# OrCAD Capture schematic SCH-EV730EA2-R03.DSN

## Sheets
1 USB & POWER: size A3; title: EV730EA0_USB&POWER; rev: 6.0; note: Ver6.1
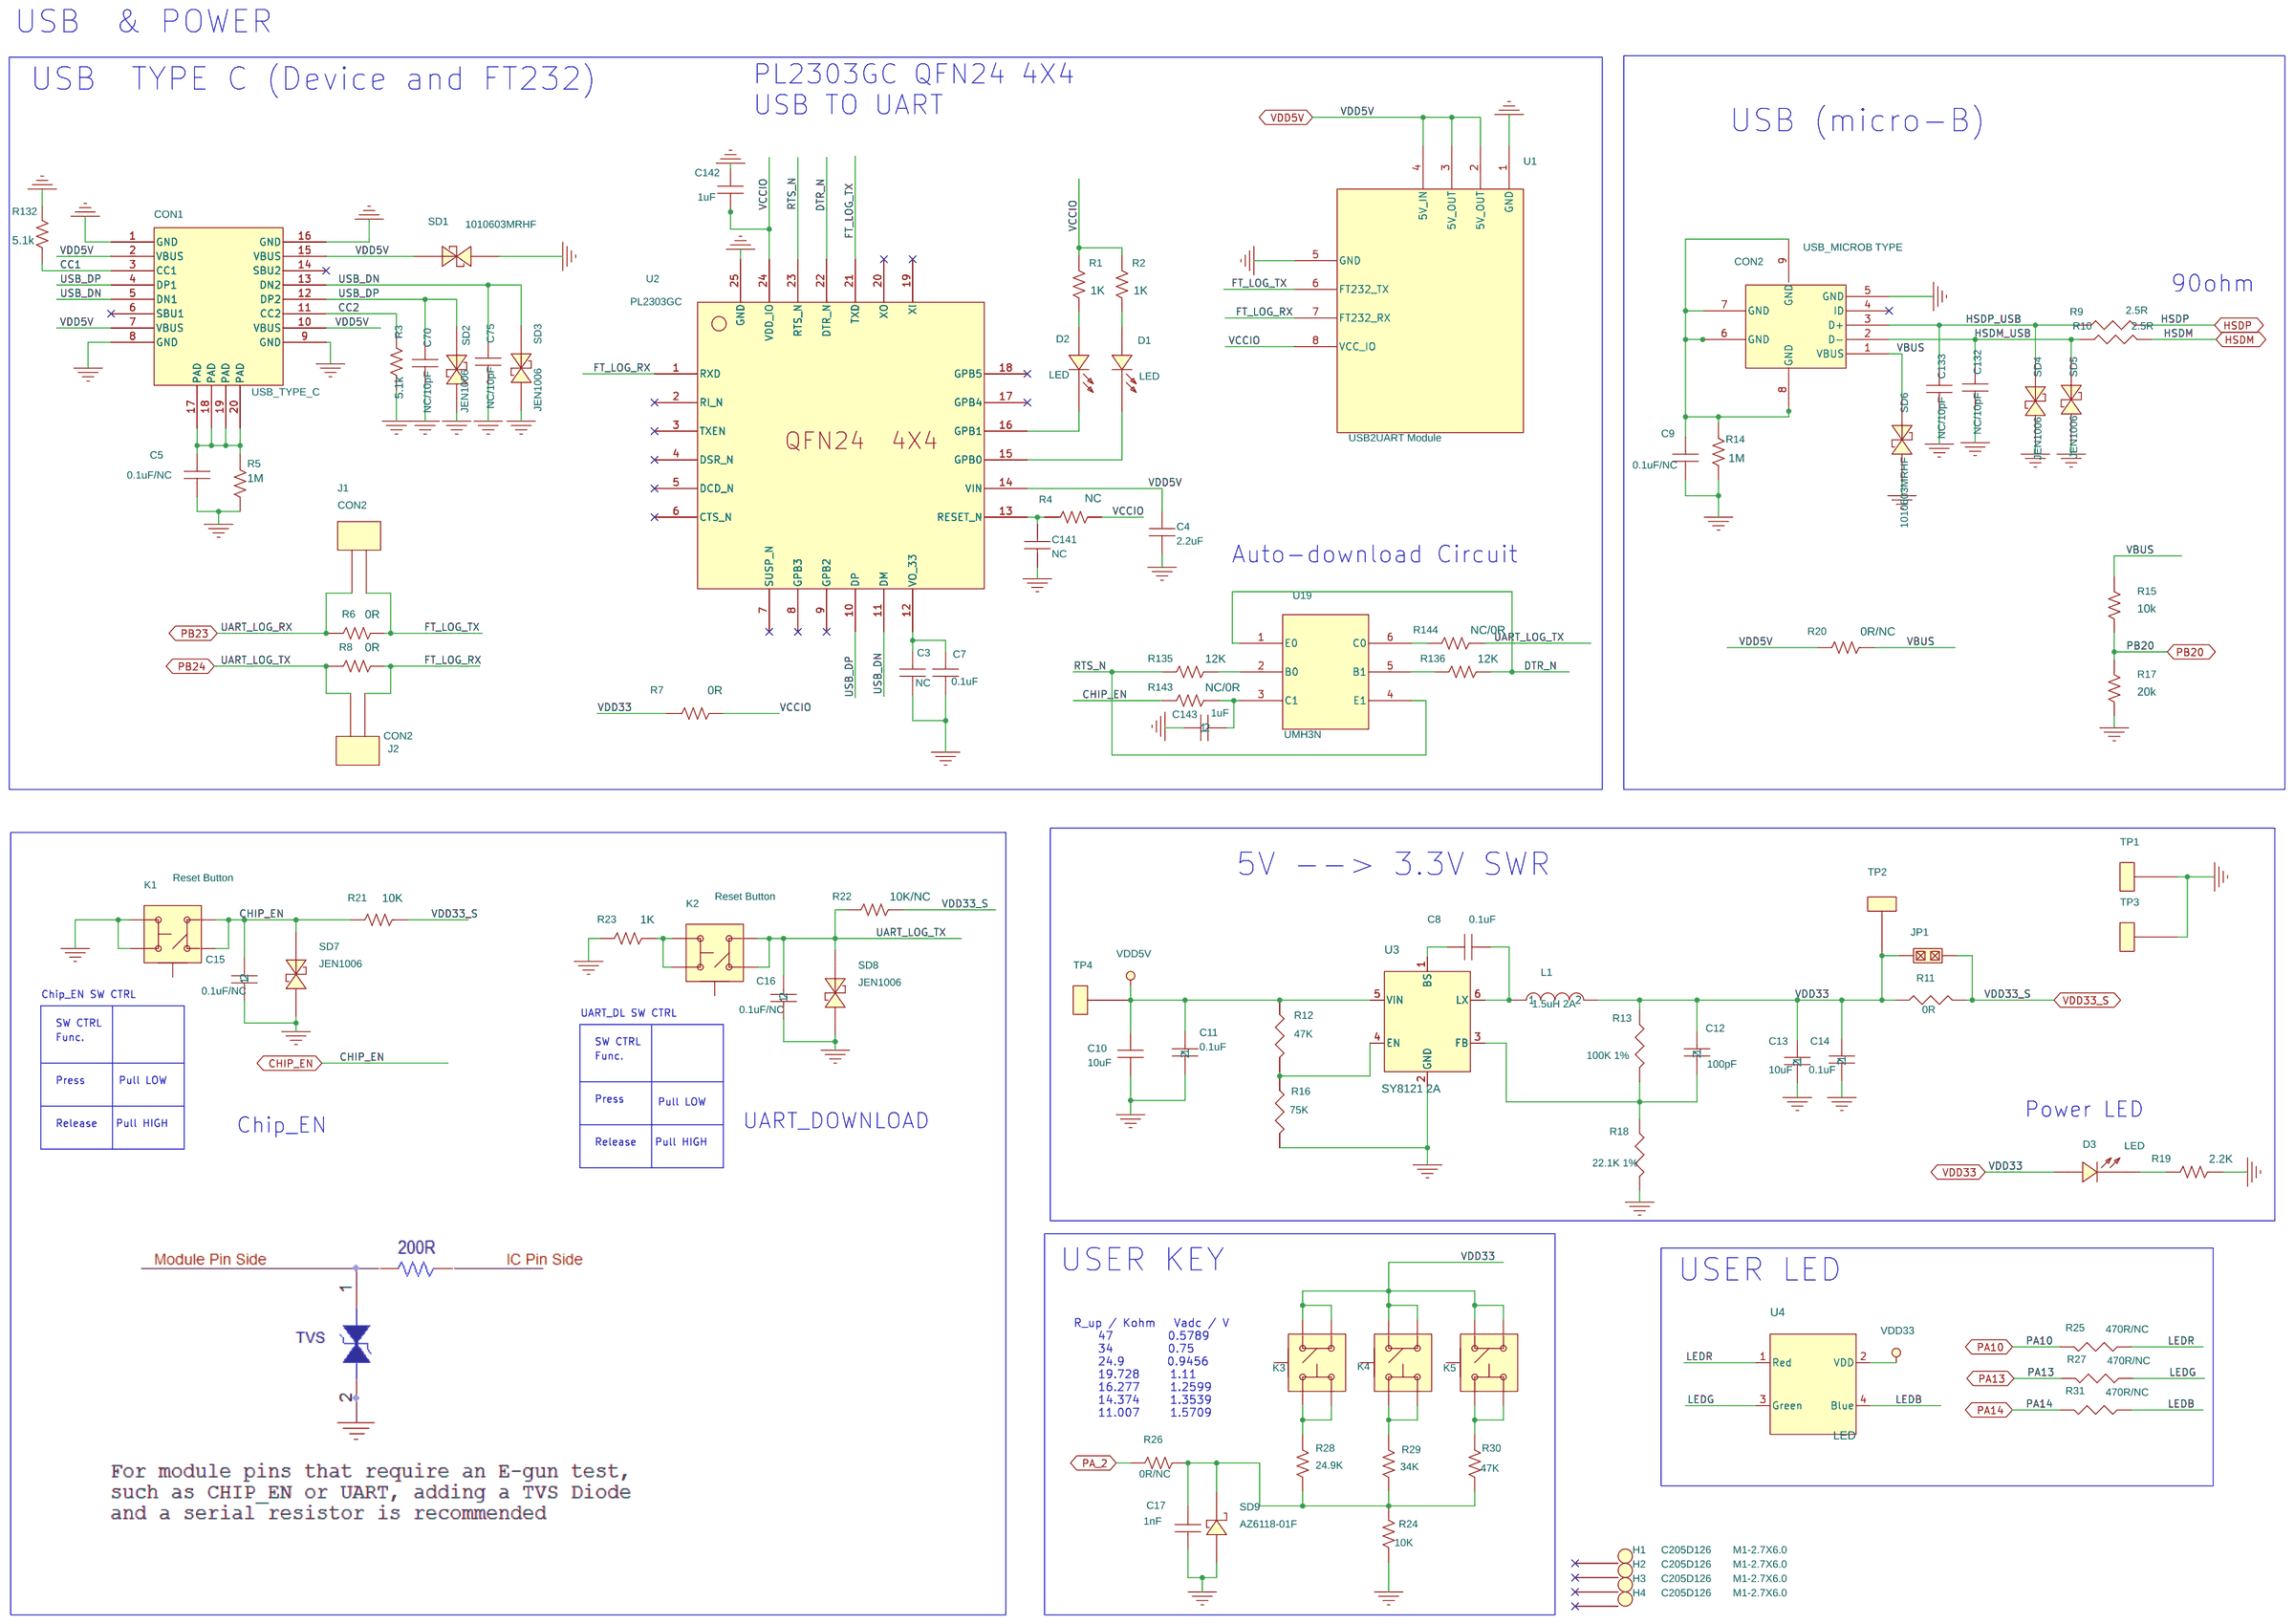
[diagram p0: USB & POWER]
2 8730E-QFN100: size A3; title: EV730EA0
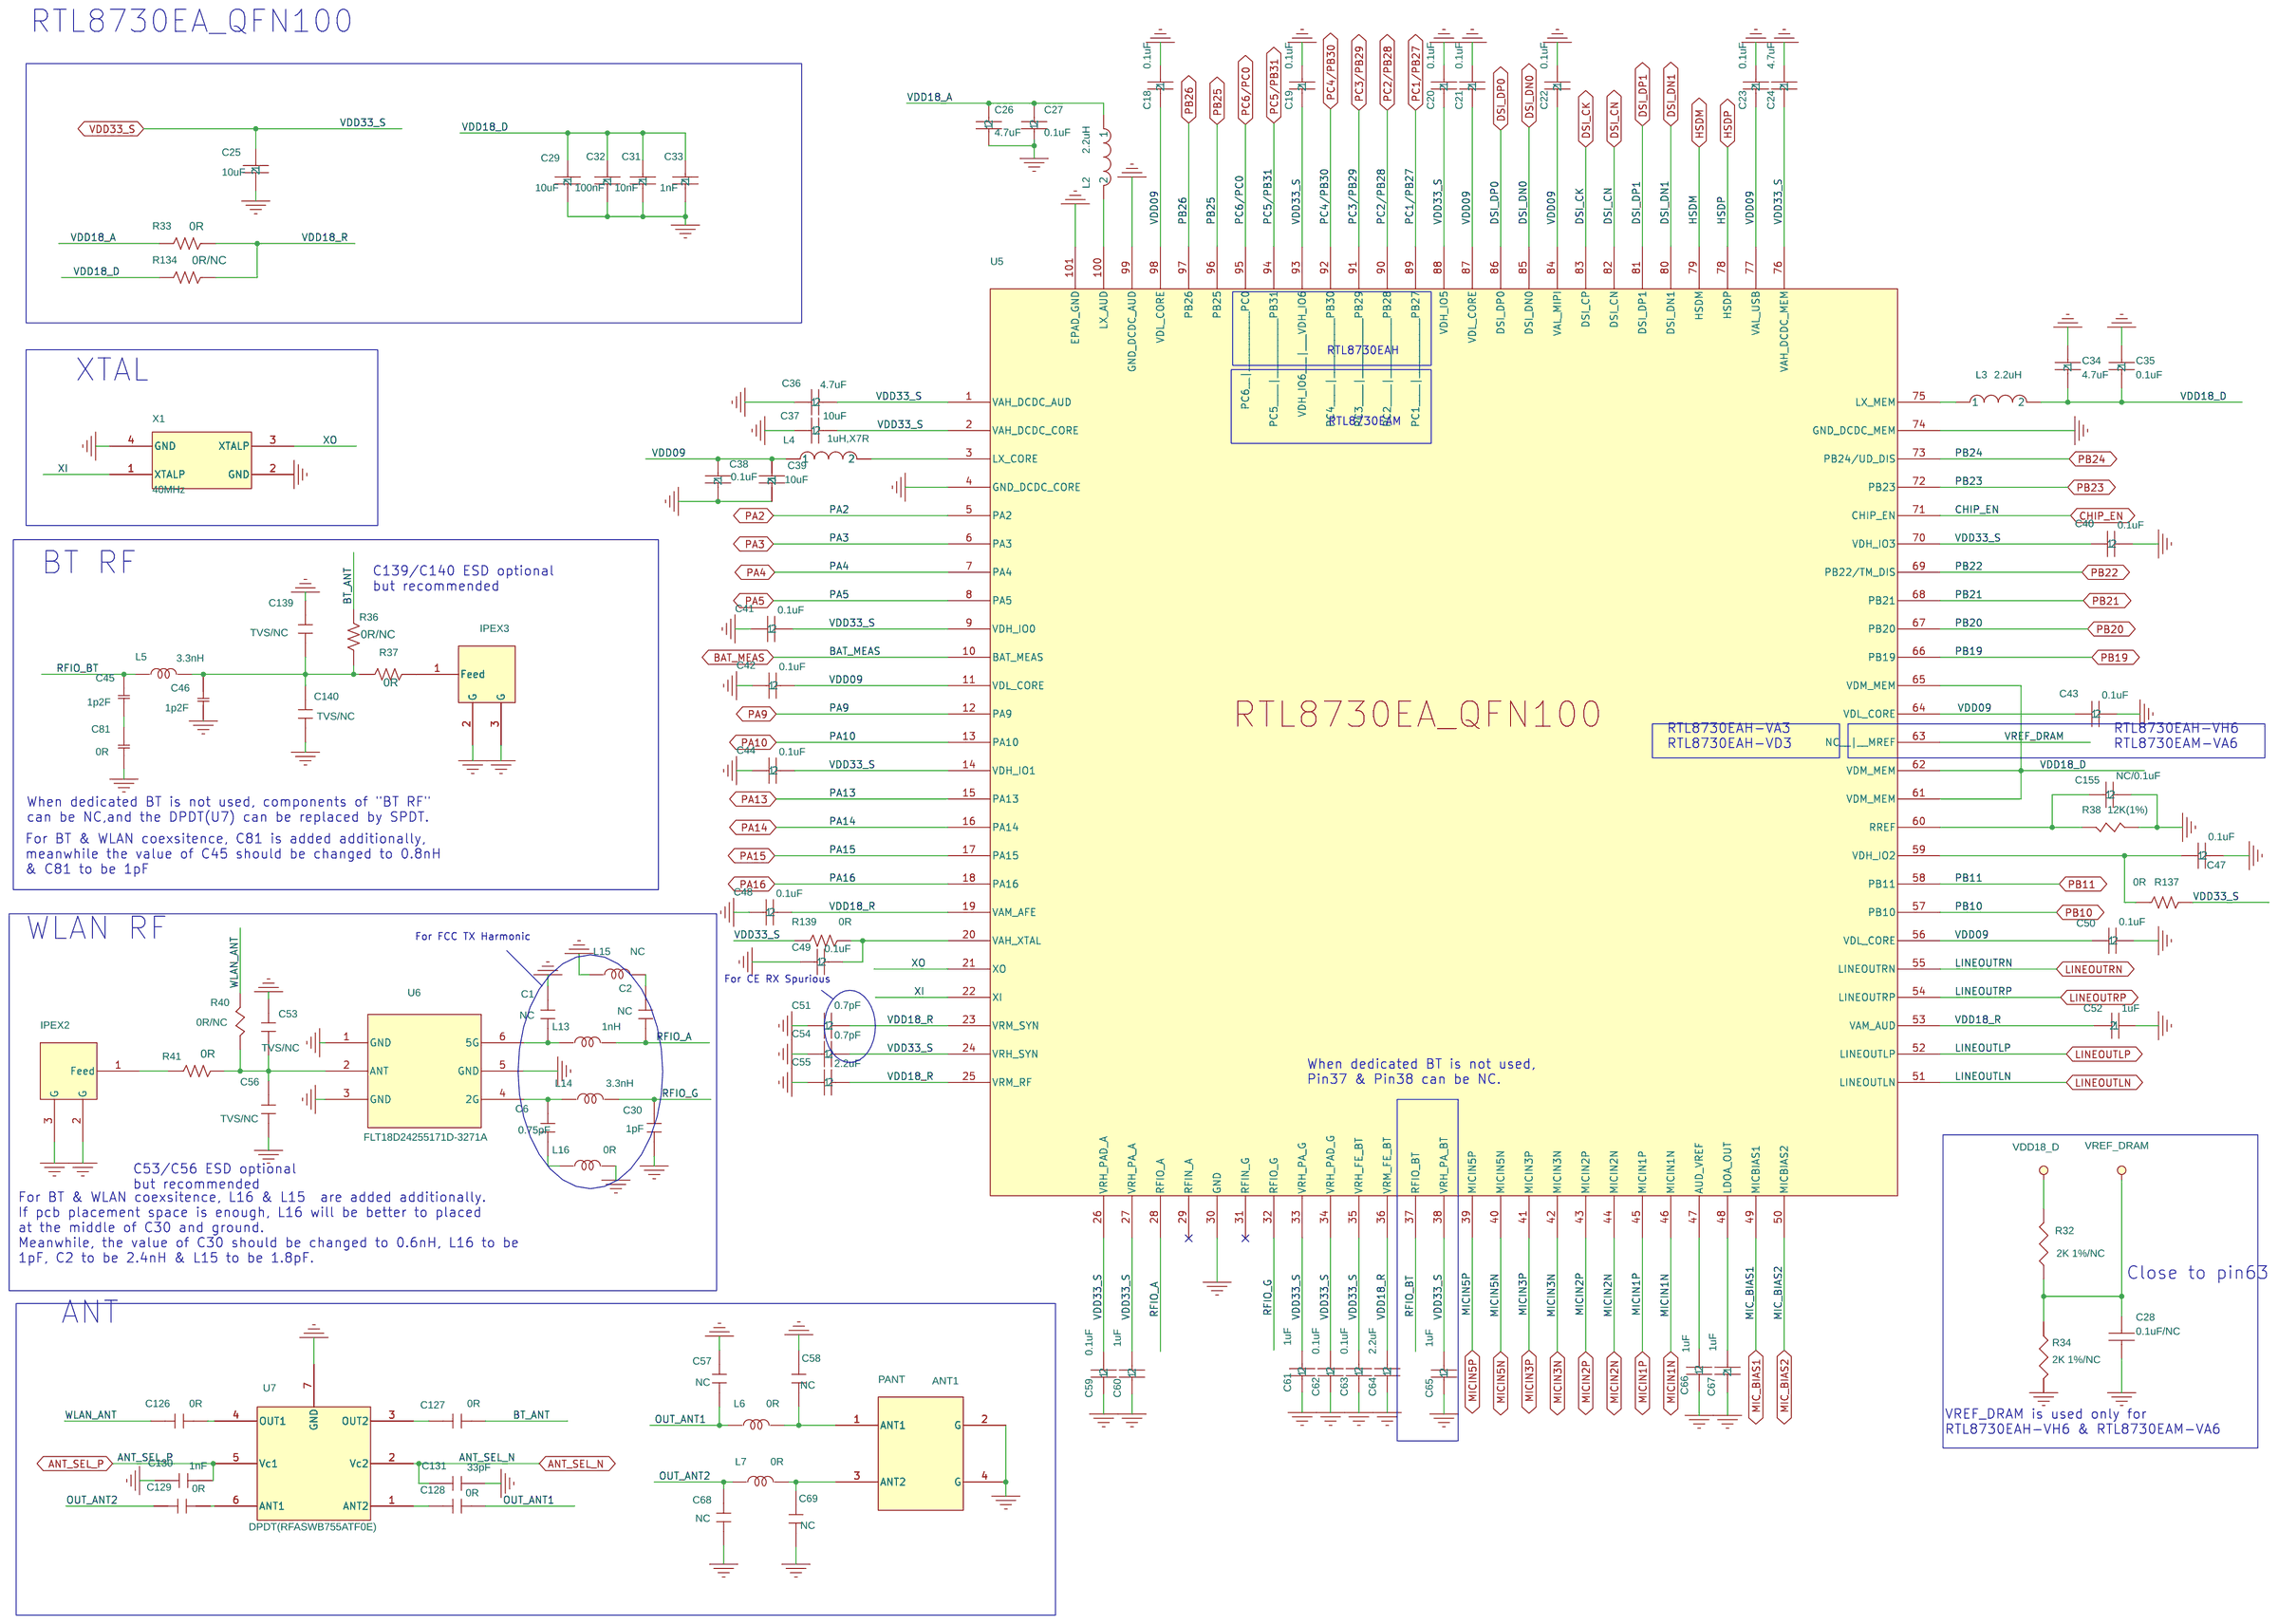
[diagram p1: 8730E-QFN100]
3 AUDIO: size A3; title: EV730EA0_AUDIO
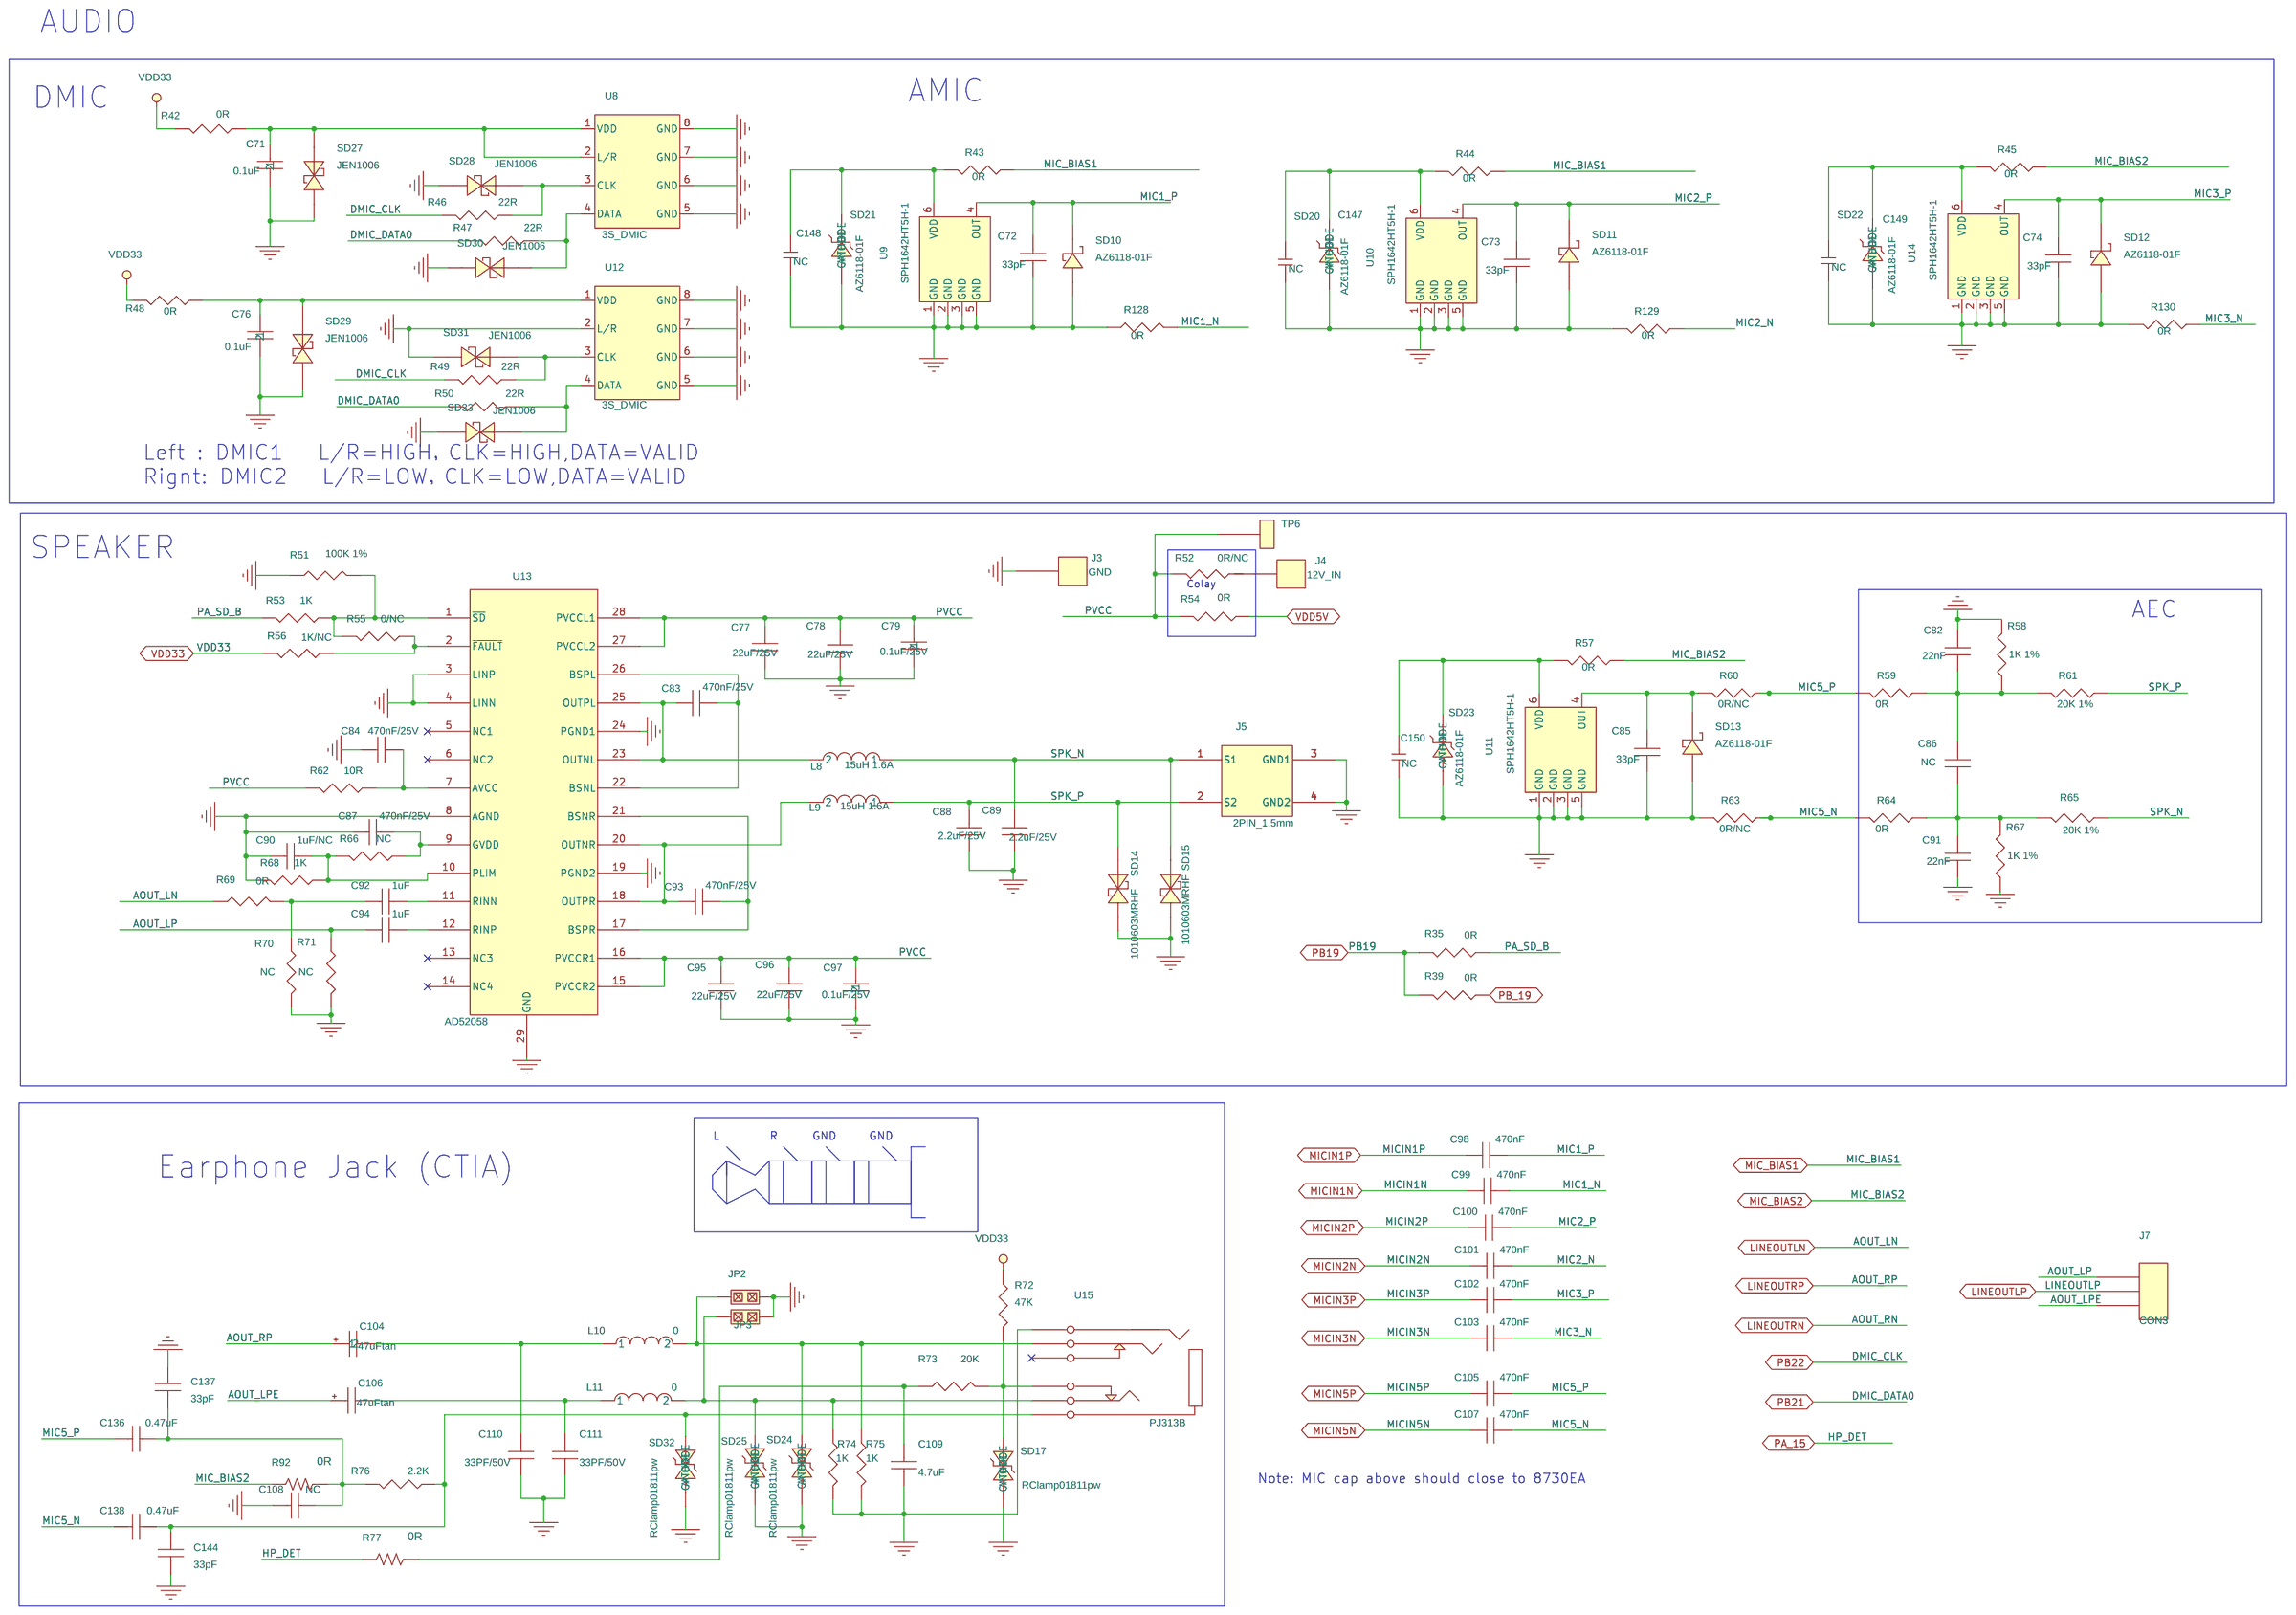
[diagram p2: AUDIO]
4 Peripheral: size A3; title: EV730EA0_Peripheral
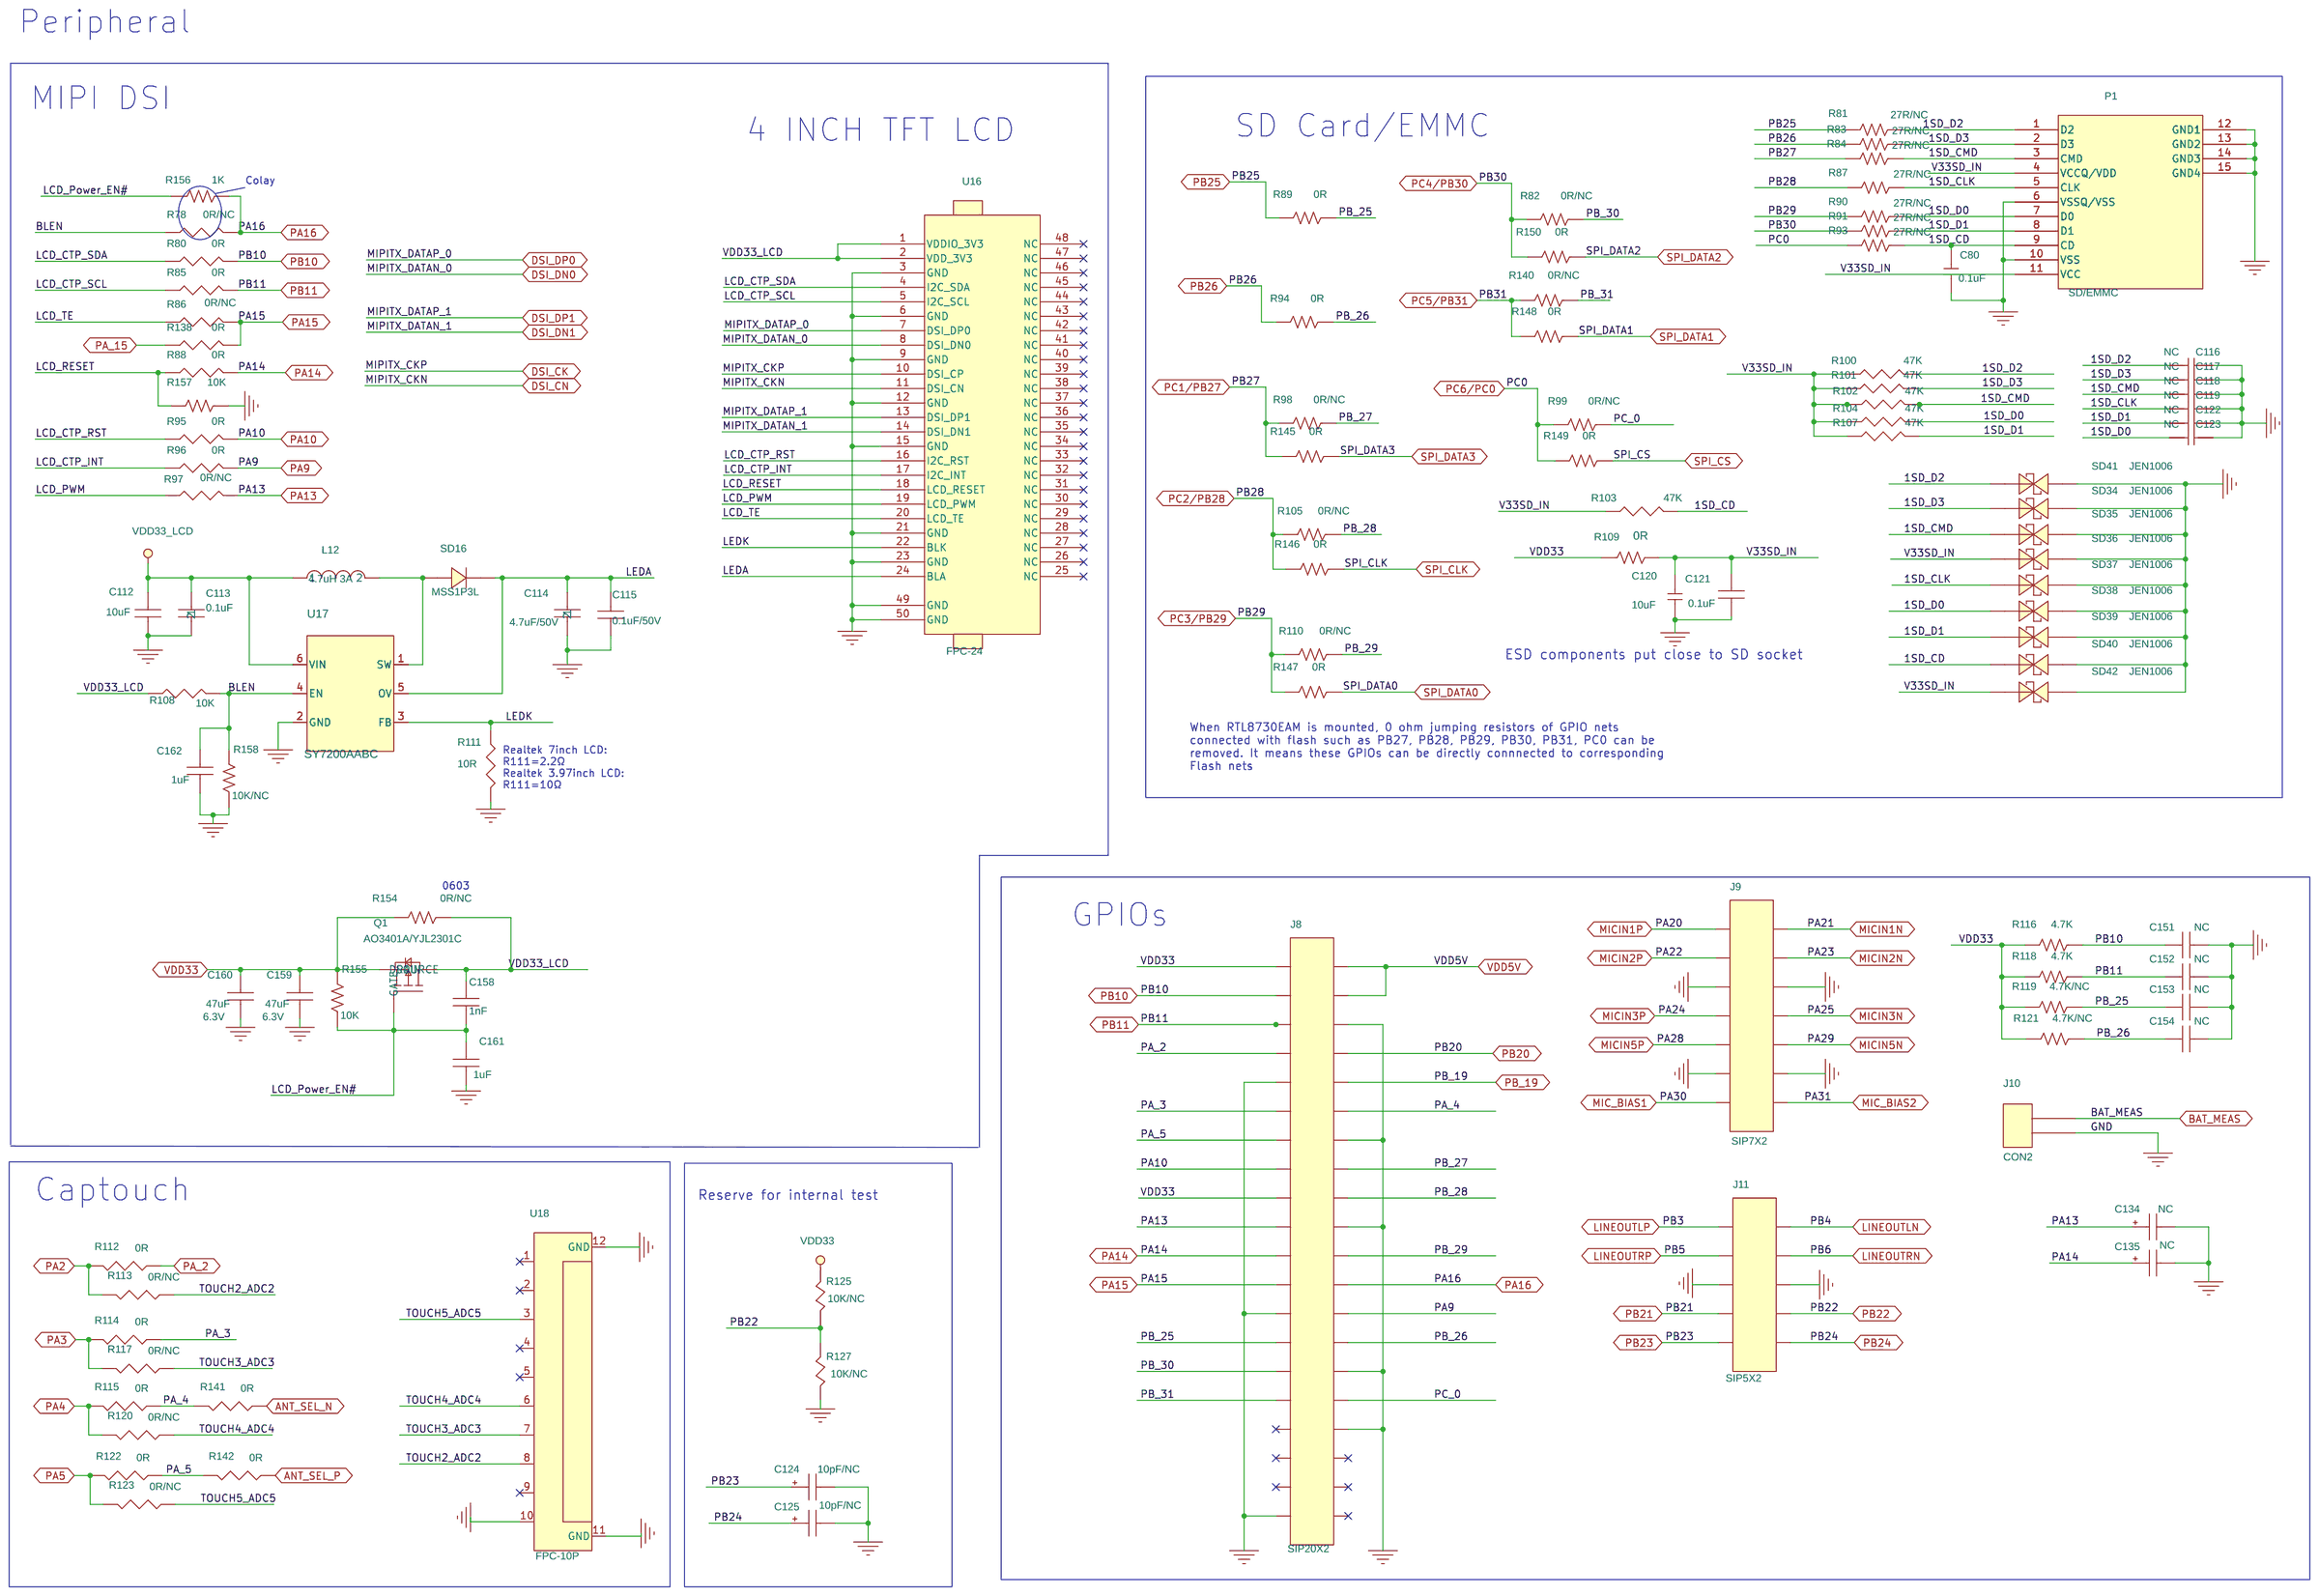
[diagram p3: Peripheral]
5 External Flash: size A; title: EV730EA0_External_FLASH
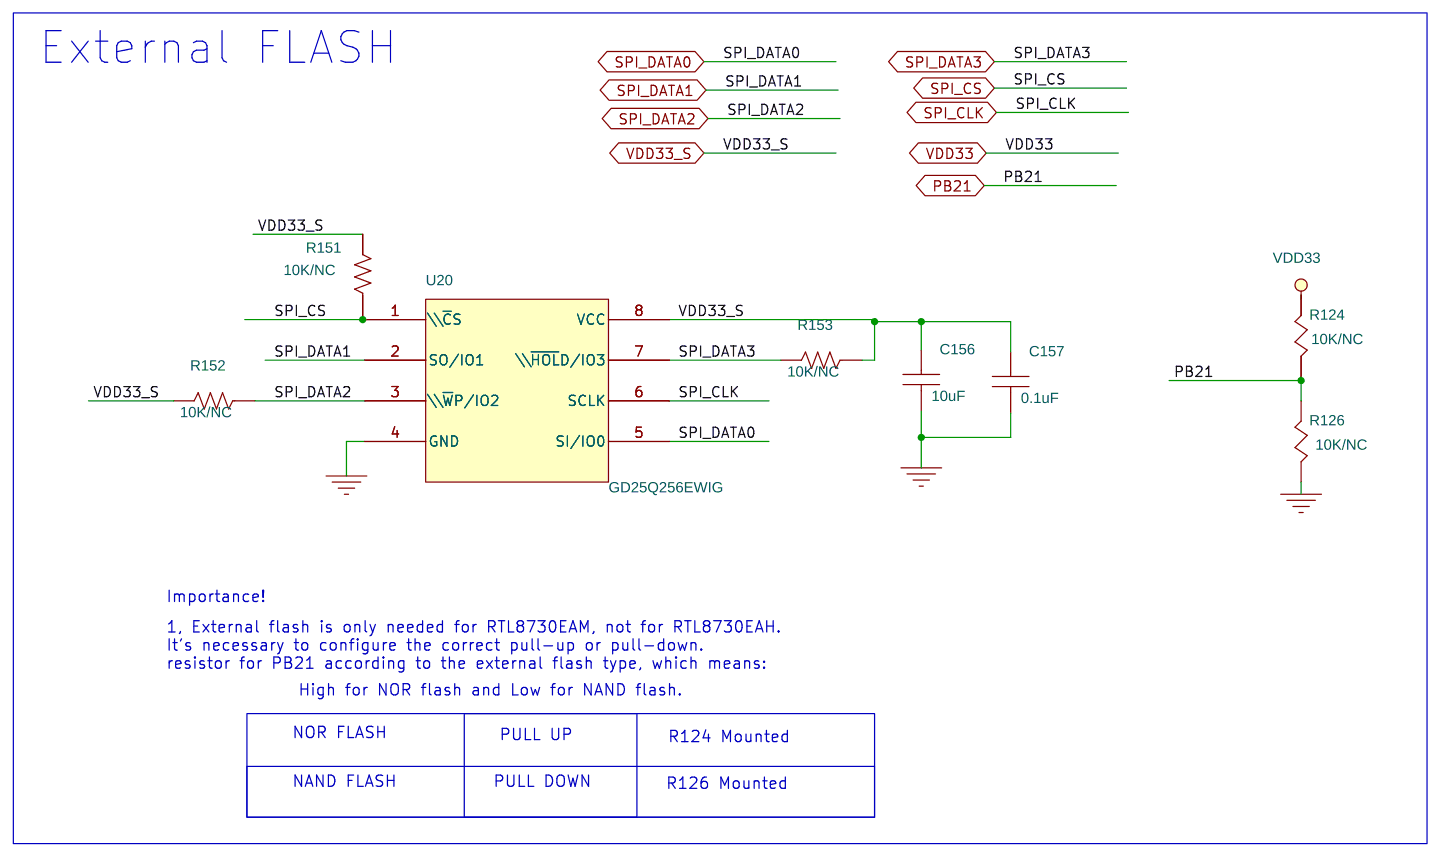
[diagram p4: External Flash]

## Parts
sheet 8730E-QFN100
ANT1  PANT  [8730EA_EVB_PANT]
C1  NC  [C0201]
C2  NC  [C0201]
C6  0.75pF  [C0201]
C18  0.1uF  [C0201]
C19  0.1uF  [C0201]
C20  0.1uF  [C0201]
C21  0.1uF  [C0201]
C22  0.1uF  [C0201]
C23  0.1uF  [C0201]
C24  4.7uF  [C0402]
C25  10uF  [C0402]
C26  4.7uF  [C0402]
C27  0.1uF  [C0201]
C28  0.1uF/NC  [C0201]
C29  10uF  [C0402]
C30  1pF  [C0201]
C31  10nF  [C0201]
C32  100nF  [C0201]
C33  1nF  [C0201]
C34  4.7uF  [C0402]
C35  0.1uF  [C0201]
C36  4.7uF  [C0402]
C37  10uF  [C0402]
C38  0.1uF  [C0201]
C39  10uF  [C0402]
C40  0.1uF  [C0201]
C41  0.1uF  [C0201]
C42  0.1uF  [C0201]
C43  0.1uF  [C0201]
C44  0.1uF  [C0201]
C45  1p2F  [C0201]
C46  1p2F  [C0201]
C47  0.1uF  [C0201]
C48  0.1uF  [C0201]
C49  0.1uF  [C0201]
C50  0.1uF  [C0201]
C51  0.7pF  [C0201]
C52  1uF  [C0201]
C53  TVS/NC  [C0201]
C54  0.7pF  [C0201]
C55  2.2uF  [C0201]
C56  TVS/NC  [C0402]
C57  NC  [C0201]
C58  NC  [C0201]
C59  0.1uF  [C0201]
C60  1uF  [C0201]
C61  1uF  [C0201]
C62  0.1uF  [C0201]
C63  0.1uF  [C0201]
C64  2.2uF  [C0201]
C65  1uF  [C0201]
C66  1uF  [C0201]
C67  1uF  [C0201]
C68  NC  [C0201]
C69  NC  [C0201]
C81  0R  [C0201]
C126  0R  [C0201]
C127  0R  [C0201]
C128  0R  [C0201]
C129  0R  [C0201]
C130  1nF  [C0201]
C131  33pF  [C0201]
C139  TVS/NC  [C0201]
C140  TVS/NC  [C0402]
C155  NC/0.1uF  [C0201]
IPEX2  TP  [IPEX-0.7X2.2-1.35]
IPEX3  TP  [IPEX-0.7X2.2-1.35]
L2  2.2uH  [L2016]
L3  2.2uH  [L2016]
L4  1uH,X7R  [L2016]
L5  3.3nH  [L0201]
L6  0R  [L0201]
L7  0R  [L0201]
L13  1nH  [L0201]
L14  3.3nH  [L0201]
L15  NC  [L0201]
L16  0R  [L0201]
R32  2K 1%/NC  [R0201]
R33  0R  [R0402]
R34  2K 1%/NC  [R0201]
R36  0R/NC  [R0201]
R37  0R  [R0201]
R38  12K(1%)  [R0201]
R40  0R/NC  [R0201]
R41  0R  [R0201]
R134  0R/NC  [R0402]
R137  0R  [R0201]
R139  0R  [R0201]
U5  RL8730EAH  [QFN100-0.35-10X10]
U6  FLT18D24255171D-3271A  [DPX1608-6-0.5-0.3X0.4]
U7  DPDT(RFASWB755ATF0E)  [DFN6_1.5x1.5MM]
X1  40MHz  [XTAL-3225]
sheet AUDIO
C71  0.1uF  [C0402]
C72  33pF  [C0402]
C73  33pF  [C0402]
C74  33pF  [C0402]
C76  0.1uF  [C0402]
C77  22uF/25V  [C0805]
C78  22uF/25V  [C0805]
C79  0.1uF/25V  [C0402]
C82  22nF  [C0402]
C83  470nF/25V  [C0402]
C84  470nF/25V  [C0402]
C85  33pF  [C0402]
C86  NC  [C0402]
C87  470nF/25V  [C0402]
C88  2.2uF/25V  [C0402]
C89  2.2uF/25V  [C0402]
C90  1uF/NC  [C0402]
C91  22nF  [C0402]
C92  1uF  [C0402]
C93  470nF/25V  [C0402]
C94  1uF  [C0402]
C95  22uF/25V  [C0805]
C96  22uF/25V  [C0805]
C97  0.1uF/25V  [C0402]
C98  470nF  [C0201]
C99  470nF  [C0201]
C100  470nF  [C0201]
C101  470nF  [C0201]
C102  470nF  [C0201]
C103  470nF  [C0201]
C104  47uFtan  [C0805-tan]
C105  470nF  [C0201]
C106  47uFtan  [C0805-tan]
C107  470nF  [C0201]
C108  NC  [C0402]
C109  4.7uF  [C0402]
C110  33PF/50V  [C0402]
C111  33PF/50V  [C0402]
C136  0.47uF  [C0402]
C137  33pF  [C0402]
C138  0.47uF  [C0402]
C144  33pF  [C0402]
C147  NC  [C0402]
C148  NC  [C0402]
C149  NC  [C0402]
C150  NC  [C0402]
J3  GND  [SIP-1P]
J4  12V_IN  [SIP-1P]
J5  2PIN_1.5mm  [2PIN-1.5MM]
J7  CON3  [SIP3-2.54]
JP2  1X2PIN  [SIP2-2.54]
JP3  1X2PIN  [SIP2-2.54]
L8  15uH 1.6A  [L5050]
L9  15uH 1.6A  [L5050]
L10  0  [L0603]
L11  0  [L0603]
R35  0R  [R0201]
R39  0R  [R0201]
R42  0R  [R0402]
R43  0R  [R0402]
R44  0R  [R0402]
R45  0R  [R0402]
R46  22R  [R0402]
R47  22R  [R0402]
R48  0R  [R0402]
R49  22R  [R0402]
R50  22R  [R0402]
R51  100K 1%  [R0402]
R52  0R/NC  [R0805]
R53  1K  [R0402]
R54  0R  [R0805]
R55  0/NC  [R0402]
R56  1K/NC  [R0402]
R57  0R  [R0402]
R58  1K 1%  [R0402]
R59  0R  [R0402]
R60  0R/NC  [R0402]
R61  20K 1%  [R0402]
R62  10R  [R0402]
R63  0R/NC  [R0402]
R64  0R  [R0402]
R65  20K 1%  [R0402]
R66  NC  [R0402]
R67  1K 1%  [R0402]
R68  1K  [R0402]
R69  0R  [R0402]
R70  NC  [R0402]
R71  NC  [R0402]
R72  47K  [R0402]
R73  20K  [R0402]
R74  1K  [R0402]
R75  1K  [R0402]
R76  2.2K  [R0402]
R77  0R  [R0402]
R92  0R  [R0402]
R128  0R  [R0402]
R129  0R  [R0402]
R130  0R  [R0402]
SD10  AZ6118-01F  [D0402-AZ6118]
SD11  AZ6118-01F  [D0402-AZ6118]
SD12  AZ6118-01F  [D0402-AZ6118]
SD13  AZ6118-01F  [D0402-AZ6118]
SD14  1010603MRHF  [D0603-PGB]
SD15  1010603MRHF  [D0603-PGB]
SD17  RClamp01811pw  [D0402-AZ6118]
SD20  AZ6118-01F  [TVS-5413-6118-5451]
SD21  AZ6118-01F  [TVS-5413-6118-5451]
SD22  AZ6118-01F  [TVS-5413-6118-5451]
SD23  AZ6118-01F  [TVS-5413-6118-5451]
SD24  RClamp01811pw  [D0402-AZ6118]
SD25  RClamp01811pw  [D0402-AZ6118]
SD27  JEN1006  [D0402-JEN]
SD28  JEN1006  [D0402-JEN]
SD29  JEN1006  [D0402-JEN]
SD30  JEN1006  [D0402-JEN]
SD31  JEN1006  [D0402-JEN]
SD32  RClamp01811pw  [D0402-AZ6118]
SD33  JEN1006  [D0402-JEN]
TP6  5V_TP  [TP]
U8  3S_DMIC  [3SM222FMT1KA]
U9  SPH1642HT5H-1  [LGA]
U10  SPH1642HT5H-1  [LGA]
U11  SPH1642HT5H-1  [LGA]
U12  3S_DMIC  [3SM222FMT1KA]
U13  AD52058  [E-TSSOP-28L]
U14  SPH1642HT5H-1  [LGA]
U15  PJ313B  [AUDIO_JACK]
sheet External Flash
C156  10uF  [C0402]
C157  0.1uF  [C0201]
R124  10K/NC  [R0402]
R126  10K/NC  [R0402]
R151  10K/NC  [R0201]
R152  10K/NC  [R0201]
R153  10K/NC  [R0201]
U20  GD25Q256EWIG  [SOIC-WSON8-1.27-0.6X2.8]
sheet Peripheral
C80  0.1uF  [C0402]
C112  10uF  [C0402]
C113  0.1uF  [C0402]
C114  4.7uF/50V  [C0805]
C115  0.1uF/50V  [C0603]
C116  NC  [C0402]
C117  NC  [C0402]
C118  NC  [C0402]
C119  NC  [C0402]
C120  10uF  [C0402]
C121  0.1uF  [C0402]
C122  NC  [C0402]
C123  NC  [C0402]
C124  10pF/NC  [C0402]
C125  10pF/NC  [C0402]
C134  NC  [C0402]
C135  NC  [C0402]
C151  NC  [C0402]
C152  NC  [C0402]
C153  NC  [C0402]
C154  NC  [C0402]
C158  1nF  [C0402]
C159  47uF  [C0603]
C160  47uF  [C0603]
C161  1uF  [C0402]
C162  1uF  [C0402]
J8  SIP20X2  [SIP20X2-2.54]
J9  SIP7X2  [SIP7X2-2.54]
J10  CON2  [SIP2-2.54]
J11  SIP5X2  [SIP5X2-2.54]
L12  4.7uH 3A  [MWSA0402]
P1  SD/EMMC  [SD_MODULE_QA]
Q1  AO3401A/YJL2301C  [SOT-23]
R78  0R/NC  [R0402]
R80  0R  [R0402]
R81  27R/NC  [R0201]
R82  0R/NC  [R0201]
R83  27R/NC  [R0201]
R84  27R/NC  [R0201]
R85  0R  [R0402]
R86  0R/NC  [R0402]
R87  27R/NC  [R0201]
R88  0R  [R0402]
R89  0R  [R0201]
R90  27R/NC  [R0201]
R91  27R/NC  [R0201]
R93  27R/NC  [R0201]
R94  0R  [R0201]
R95  0R  [R0402]
R96  0R  [R0402]
R97  0R/NC  [R0402]
R98  0R/NC  [R0201]
R99  0R/NC  [R0201]
R100  47K  [R0402]
R101  47K  [R0402]
R102  47K  [R0402]
R103  47K  [R0402]
R104  47K  [R0402]
R105  0R/NC  [R0201]
R107  47K  [R0402]
R108  10K  [R0402]
R109  0R  [R0402]
R110  0R/NC  [R0201]
R111  10R  [R0402]
R112  0R  [R0402]
R113  0R/NC  [R0402]
R114  0R  [R0402]
R115  0R  [R0402]
R116  4.7K  [R0402]
R117  0R/NC  [R0402]
R118  4.7K  [R0402]
R119  4.7K/NC  [R0402]
R120  0R/NC  [R0402]
R121  4.7K/NC  [R0402]
R122  0R  [R0402]
R123  0R/NC  [R0402]
R125  10K/NC  [R0402]
R127  10K/NC  [R0402]
R138  0R  [R0402]
R140  0R/NC  [R0201]
R141  0R  [R0402]
R142  0R  [R0402]
R145  0R  [R0201]
R146  0R  [R0201]
R147  0R  [R0201]
R148  0R  [R0201]
R149  0R  [R0201]
R150  0R  [R0201]
R154  0R/NC  [R0603]
R155  10K  [R0402]
R156  1K  [R0402]
R157  10K  [R0402]
R158  10K/NC  [R0402]
SD16  MSS1P3L  [DO-219AD]
SD34  JEN1006  [D0402-JEN]
SD35  JEN1006  [D0402-JEN]
SD36  JEN1006  [D0402-JEN]
SD37  JEN1006  [D0402-JEN]
SD38  JEN1006  [D0402-JEN]
SD39  JEN1006  [D0402-JEN]
SD40  JEN1006  [D0402-JEN]
SD41  JEN1006  [D0402-JEN]
SD42  JEN1006  [D0402-JEN]
U16  FPC-24  [FPC-MIPI-24P-15P]
U17  SY7200AABC  [SOT-23-6]
U18  FPC-10P  [FPC-10-1mm]
sheet USB & POWER
C3  NC  [C0402]
C4  2.2uF  [C0402]
C5  0.1uF/NC  [C0402]
C7  0.1uF  [C0402]
C8  0.1uF  [C0402]
C9  0.1uF/NC  [C0402]
C10  10uF  [C0402]
C11  0.1uF  [C0402]
C12  100pF  [C0402]
C13  10uF  [C0402]
C14  0.1uF  [C0402]
C15  0.1uF/NC  [C0402]
C16  0.1uF/NC  [C0402]
C17  1nF  [C0402]
C70  NC/10pF  [C0201]
C75  NC/10pF  [C0201]
C132  NC/10pF  [C0201]
C133  NC/10pF  [C0201]
C141  NC  [C0402]
C142  1uF  [C0402]
C143  1uF  [C0402]
CON1  USB_TYPE_C  [USB-C-SMT]
CON2  USB_MICROB TYPE  [USB-MICRO-B-SMT-3]
D1  LED  [LED-0603]
D2  LED  [LED-0603]
D3  LED  [LED-0805]
H1  C205D126  [M1-2.7X6.0]
H2  C205D126  [M1-2.7X6.0]
H3  C205D126  [M1-2.7X6.0]
H4  C205D126  [M1-2.7X6.0]
J1  CON2  [SIP2-2.54]
J2  CON2  [SIP2-2.54]
JP1  1X2PIN  [SIP2-2.54]
K1  Reset Button  [SW-4P-3X4]
K2  Reset Button  [SW-4P-3X4]
K3  Reset Button  [SW-4P-3X4]
K4  Reset Button  [SW-4P-3X4]
K5  Reset Button  [SW-4P-3X4]
L1  1.5uH 2A  [MWSA0402]
R1  1K  [R0402]
R2  1K  [R0402]
R3  5.1k  [R0402]
R4  NC  [R0402]
R5  1M  [R0402]
R6  0R  [R0402]
R7  0R  [R0402]
R8  0R  [R0402]
R9  2.5R  [R0402]
R10  2.5R  [R0402]
R11  0R  [R0805]
R12  47K  [R0402]
R13  100K 1%  [R0402]
R14  1M  [R0402]
R15  10k  [R0402]
R16  75K  [R0402]
R17  20k  [R0402]
R18  22.1K 1%  [R0402]
R19  2.2K  [R0402]
R20  0R/NC  [R0603]
R21  10K  [R0201]
R22  10K/NC  [R0201]
R23  1K  [R0402]
R24  10K  [R0402]
R25  470R/NC  [R0402]
R26  0R/NC  [R0402]
R27  470R/NC  [R0402]
R28  24.9K  [R0402]
R29  34K  [R0402]
R30  47K  [R0402]
R31  470R/NC  [R0402]
R132  5.1k  [R0402]
R135  12K  [R0402]
R136  12K  [R0402]
R143  NC/0R  [R0402]
R144  NC/0R  [R0402]
SD1  1010603MRHF  [D0603-PGB]
SD2  JEN1006  [D0402-JEN]
SD3  JEN1006  [D0402-JEN]
SD4  JEN1006  [D0402-JEN]
SD5  JEN1006  [D0402-JEN]
SD6  1010603MRHF  [D0603-PGB]
SD7  JEN1006  [D0402-JEN]
SD8  JEN1006  [D0402-JEN]
SD9  AZ6118-01F  [D0402-AZ6118]
TP1  5V_TP  [TP]
TP2  5V_TP  [TP]
TP3  5V_TP  [TP]
TP4  5V_TP  [TP]
U1  USB2UART Module  [MODULE_USB_FT232_2]
U2  PL2303GC  [UQFN24-4X4-PL2303GC]
U3  SY8121 2A  [SOT-23-6]
U4  LED  [LED3-3.5X2.8]
U19  UMH3N  [SOT-363]

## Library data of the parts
ANT1 = TP_2
C1 C2 C6 C30 C53 C56-C58 C68 C69 C126-C131 C139 C140 = C_402
C18 = C_v2_27: X5R, ∮20%, 6.3V; Manufacturer: WALSIN; Part Number: 0805X106K6R3CT; Unit Price(USD): 0.01048
C19 = C_v2_6: X5R, ∮20%, 6.3V; Manufacturer: WALSIN; Part Number: 0805X106K6R3CT; Unit Price(USD): 0.01048
C20 = C_v2_32: X5R, ∮20%, 6.3V; Manufacturer: WALSIN; Part Number: 0805X106K6R3CT; Unit Price(USD): 0.01048
C21 = C_v2_19: X5R, ∮20%, 6.3V; Manufacturer: WALSIN; Part Number: 0805X106K6R3CT; Unit Price(USD): 0.01048
C22 = C_v2_2: X5R, ∮20%, 6.3V; Manufacturer: WALSIN; Part Number: 0805X106K6R3CT; Unit Price(USD): 0.01048
C23 = C_v2_29: X5R, ∮20%, 6.3V; Manufacturer: WALSIN; Part Number: 0805X106K6R3CT; Unit Price(USD): 0.01048
C24 = C_v2_42: X5R, ∮20%, 6.3V; Manufacturer: WALSIN; Part Number: 0805X106K6R3CT; Unit Price(USD): 0.01048
C25 = C_v2_36: X5R, ∮20%, 6.3V; Manufacturer: WALSIN; Part Number: 0805X106K6R3CT; Unit Price(USD): 0.01048
C26 = C_v2_37: X5R, ∮20%, 6.3V; Manufacturer: WALSIN; Part Number: 0805X106K6R3CT; Unit Price(USD): 0.01048
C27 = C_v2_16: X5R, ∮20%, 6.3V; Manufacturer: WALSIN; Part Number: 0805X106K6R3CT; Unit Price(USD): 0.01048
C28 C100 = CAP_NP
C29 = C_v2_22: X5R, ∮20%, 6.3V; Manufacturer: WALSIN; Part Number: 0805X106K6R3CT; Unit Price(USD): 0.01048
C31 = C_v2_4: X5R, ∮20%, 6.3V; Manufacturer: WALSIN; Part Number: 0805X106K6R3CT; Unit Price(USD): 0.01048
C32 = C_v2_7: X5R, ∮20%, 6.3V; Manufacturer: WALSIN; Part Number: 0805X106K6R3CT; Unit Price(USD): 0.01048
C33 = C_v2_11: X5R, ∮20%, 6.3V; Manufacturer: WALSIN; Part Number: 0805X106K6R3CT; Unit Price(USD): 0.01048
C34 = C_v2_3: X5R, ∮20%, 6.3V; Manufacturer: WALSIN; Part Number: 0805X106K6R3CT; Unit Price(USD): 0.01048
C35 = C_v2: X5R, ∮20%, 6.3V; Manufacturer: WALSIN; Part Number: 0805X106K6R3CT; Unit Price(USD): 0.01048
C36 = C_v2_24: X5R, ∮20%, 6.3V; Manufacturer: WALSIN; Part Number: 0805X106K6R3CT; Unit Price(USD): 0.01048
C37 = C_v2_13: X5R, ∮20%, 6.3V; Manufacturer: WALSIN; Part Number: 0805X106K6R3CT; Unit Price(USD): 0.01048
C38 = C_v2_17: X5R, ∮20%, 6.3V; Manufacturer: WALSIN; Part Number: 0805X106K6R3CT; Unit Price(USD): 0.01048
C39 = C_v2_21: X5R, ∮20%, 6.3V; Manufacturer: WALSIN; Part Number: 0805X106K6R3CT; Unit Price(USD): 0.01048
C40 = C_v2_20: X5R, ∮20%, 6.3V; Manufacturer: WALSIN; Part Number: 0805X106K6R3CT; Unit Price(USD): 0.01048
C41 = C_v2_26: X5R, ∮20%, 6.3V; Manufacturer: WALSIN; Part Number: 0805X106K6R3CT; Unit Price(USD): 0.01048
C42 = C_v2_34: X5R, ∮20%, 6.3V; Manufacturer: WALSIN; Part Number: 0805X106K6R3CT; Unit Price(USD): 0.01048
C43 = C_v2_18: X5R, ∮20%, 6.3V; Manufacturer: WALSIN; Part Number: 0805X106K6R3CT; Unit Price(USD): 0.01048
C44 = C_v2_40: X5R, ∮20%, 6.3V; Manufacturer: WALSIN; Part Number: 0805X106K6R3CT; Unit Price(USD): 0.01048
C45 C46 C81 = C0201: PN: *; Vendor: *
C47 = C_v2_41: X5R, ∮20%, 6.3V; Manufacturer: WALSIN; Part Number: 0805X106K6R3CT; Unit Price(USD): 0.01048
C48 = C_v2_8: X5R, ∮20%, 6.3V; Manufacturer: WALSIN; Part Number: 0805X106K6R3CT; Unit Price(USD): 0.01048
C49 = C_v2_14: X5R, ∮20%, 6.3V; Manufacturer: WALSIN; Part Number: 0805X106K6R3CT; Unit Price(USD): 0.01048
C50 = C_v2_1: X5R, ∮20%, 6.3V; Manufacturer: WALSIN; Part Number: 0805X106K6R3CT; Unit Price(USD): 0.01048
C51 = C_v2_23: X5R, ∮20%, 6.3V; Manufacturer: WALSIN; Part Number: 0805X106K6R3CT; Unit Price(USD): 0.01048
C52 = C_v2_31: NPO, ∮5%, 50V; Manufacturer: WALSIN; Part Number: 0402N180J500LT; Unit Price(USD): 0.00076
C54 = C_v2_28: X5R, ∮20%, 6.3V; Manufacturer: WALSIN; Part Number: 0805X106K6R3CT; Unit Price(USD): 0.01048
C55 = C_v2_5: X5R, ∮20%, 6.3V; Manufacturer: WALSIN; Part Number: 0805X106K6R3CT; Unit Price(USD): 0.01048
C59 = C_v2_38: NPO, ∮5%, 50V; Manufacturer: WALSIN; Part Number: 0402N180J500LT; Unit Price(USD): 0.00076
C60 = C_v2_10: NPO, ∮5%, 50V; Manufacturer: WALSIN; Part Number: 0402N180J500LT; Unit Price(USD): 0.00076
C61 = C_v2_33: NPO, ∮5%, 50V; Manufacturer: WALSIN; Part Number: 0402N180J500LT; Unit Price(USD): 0.00076
C62 = C_v2_39: NPO, ∮5%, 50V; Manufacturer: WALSIN; Part Number: 0402N180J500LT; Unit Price(USD): 0.00076
C63 = C_v2_12: NPO, ∮5%, 50V; Manufacturer: WALSIN; Part Number: 0402N180J500LT; Unit Price(USD): 0.00076
C64 = C_v2_35: NPO, ∮5%, 50V; Manufacturer: WALSIN; Part Number: 0402N180J500LT; Unit Price(USD): 0.00076
C65 = C_v2_15: NPO, ∮5%, 50V; Manufacturer: WALSIN; Part Number: 0402N180J500LT; Unit Price(USD): 0.00076
C66 = C_v2_25: NPO, ∮5%, 50V; Manufacturer: WALSIN; Part Number: 0402N180J500LT; Unit Price(USD): 0.00076
C67 = C_v2_9: X5R, ∮20%, 6.3V; Manufacturer: WALSIN; Part Number: 0805X106K6R3CT; Unit Price(USD): 0.01048
C155 = C_v2_30: X5R, ∮20%, 6.3V; Manufacturer: WALSIN; Part Number: 0805X106K6R3CT; Unit Price(USD): 0.01048
IPEX2 IPEX3 = TP_3
L2 L8 = INDUCTOR_1
L1 L3 L10 L12 = INDUCTOR
L4 L9 = INDUCTOR_2
L5-L7 L13-L16 = L0402_1.7NH_ACX
R26 R32 R34 R118 = R_3
R33 R134 = RES_V: Manufacturer: WALSIN; Part Number: WR04X1004FTL; Unit Price(USD): 0.00032
R3 R6 R8 R36 R37 R41 R77 R92 R132 = RES_V: Manufacturer: WALSIN; Part Number: WR04X1002FTL; Unit Price(USD): 0.00032
R38 R40 R124-R127 = R0402_1.06K_WALSIN
R28 R119 R137 = R
R30 R116 R139 = R_1
U5 = RL5760_90
U6 = 9346_7
U7 = 9346_12
X1 = 9346_0
C11 C71 C113 = C_v2_1: X7R, ∮10%, 10V; Manufacturer: WALSIN; Part Number: 0402B104K100CT; Unit Price(USD): 0.0008
C72 = CAP_NP_21
C73 = CAP_NP_3
C74 = CAP_NP_15
C14 C76 = C_v2_3: X7R, ∮10%, 10V; Manufacturer: WALSIN; Part Number: 0402B104K100CT; Unit Price(USD): 0.0008
C77 = CAP_NP_9: Y5V, ∮20%, 6.3; Manufacturer: WALSIN; Part Number: 0805F226Z6R3CT; Unit Price(USD): 0.01921
C78 = CAP_NP_23: Y5V, ∮20%, 6.3; Manufacturer: WALSIN; Part Number: 0805F226Z6R3CT; Unit Price(USD): 0.01921
C16 C79 C114 = C_v2: X7R, ∮10%, 10V; Manufacturer: WALSIN; Part Number: 0402B104K100CT; Unit Price(USD): 0.0008
C82 = CAP_NP_27
C83 = CAP_NP_7
C84 = CAP_NP_18
C85 = CAP_NP_35
C86 = CAP_NP_13
C87 = CAP_NP_14
C88 = CAP_NP_5
C89 = CAP_NP_16
C90 = CAP_NP_28
C91 = CAP_NP_34
C92 = CAP_NP_4
C93 = CAP_NP_10
C94 = CAP_NP_31
C95 = CAP_NP_24: Y5V, ∮20%, 6.3; Manufacturer: WALSIN; Part Number: 0805F226Z6R3CT; Unit Price(USD): 0.01921
C96 = CAP_NP_29: Y5V, ∮20%, 6.3; Manufacturer: WALSIN; Part Number: 0805F226Z6R3CT; Unit Price(USD): 0.01921
C15 C97 = C_v2_2: X7R, ∮10%, 10V; Manufacturer: WALSIN; Part Number: 0402B104K100CT; Unit Price(USD): 0.0008
C98 = CAP_NP_30
C99 = CAP_NP_33
C17 C101 = CAP_NP_2
C102 = CAP_NP_6
C103 = CAP_NP_8
C104 = CAP_NP_0
C105 = CAP_NP_19
C106 C144 = CAP_NP_1
C107 = CAP_NP_22
C108 = CAP_NP_12
C109 = CAP_NP_25
C110 = CAP_NP_17
C111 = CAP_NP_20
C136 = CAP_NP_26
C137 = CAP_NP_11
C138 = CAP_NP_32
C117 C147 = C_2
C120 C148 = C
C123 C149 = C_3
C80 C150 = C_1
J3 J4 = CON1
J5 = 2PIN_1.5mm
J7 = CON2_0
JP1-JP3 = 1X2PIN
L11 = INDUCTOR_3
R35 R115 = R_v2_23
R39 = R_v2_32
R42 R97 = R_v2_24
R43 R102 = R_v2_18
R9 R44 R108 = R_v2_3
R45 = R_v2_27
R46 R86 = R_v2_11
R47 = R_v2_38
R48 = R_v2_31
R31 R49 R96 = R_v2_1
R50 R95 = R_v2_12
R51 R141 = R_v2_15
R52 = R_v2_35
R53 R88 = R_v2_16
R54 = R_v2_34
R55 R114 = R_v2_14
R56 = R_v2_39
R57 = R_v2_37
R58 R142 = R_v2_6
R59 R107 = R_v2_5
R60 = R_v2_26
R27 R61 R104 = R_v2
R62 R80 = R_v2_9
R63 = R_v2_30
R64 R117 = R_v2_7
R25 R65 R123 = R_v2_4
R66 R120 = R_v2_21
R67 = R_v2_29
R68 = R_v2_33
R69 = R_v2_28
R70 R122 = R_v2_13
R71 R101 = R_v2_10
R72 = R_v2_36
R73 R112 = R_v2_25
R10 R74 R100 = R_v2_2
R75 R85 = R_v2_8
R76 R78 = R_v2_20
R103 R128 = R_v2_17
R129 R138 = R_v2_19
R113 R130 = R_v2_22
SD9-SD13 = Uni-directional_ESD_0: Uni-directional, 2V; Manufacturer: Amazing; Datasheet: \\172.29.17.1\cn\WLAN\WLAN2\boarddesignLIB\01_component_database\Datasheet\TVS\TVS_Amazing_AZ6118-01F-V1.0 1.pdf
SD1 SD6 SD14 SD15 = Bi-directional_ESD_0: Bi-directional, 8KV; Manufacturer: LittleFuse; Part Number: PGB1010603; Datasheet: \\172.29.17.1\cn\WLAN\WLAN2\boarddesignLIB\01_component_database\Datasheet\TVS\TVS_Littlefuse_101060.pdf
SD17 = DIODE_SCHOTTKY_8
SD20-SD23 = DIODE_SCHOTTKY_5
SD24 = DIODE_SCHOTTKY_11
SD25 = DIODE_SCHOTTKY_10
SD2-SD5 SD7 SD8 SD27-SD31 SD33-SD42 = Bi-directional_ESD_0: Bi-directional, 3.3V; Manufacturer: JDT Fuse; Part Number: JEN1006-3.3V-ULC; Datasheet: \\172.29.17.1\cn\WLAN\WLAN2\boarddesignLIB\01_component_database\Datasheet\TVS\TVS_JDTfuse_JEN1006-3.3V-ULC.pdf
SD32 = DIODE_SCHOTTKY_9
TP1-TP4 TP6 = TEST_POINT
U8 = 3S_DMIC_2
U9-U11 U14 = SPH1642HT5H-1_3
U12 = 3S_DMIC_3
U13 = AD52066_3
U15 = PJ313B
C156 = CAPACITOR_NON-POL_0: ±20%,10V,X5R; Manufacturer: WALSIN; Part Number: 0402X106M100CT; Voltage: 10V; Datasheet: \\172.29.17.1\cn\WLAN\WLAN2\boarddesignLIB\53_component_database\Datasheet\Capacitor\Capacitor_Walsin_MLCC.pdf
C157 = CAPACITOR_NON-POL_0: ±10%,10V,X5R; Manufacturer: WALSIN; Part Number: 0201X104K100CT; Voltage: 10V; Datasheet: \\172.29.17.1\cn\WLAN\WLAN2\boarddesignLIB\04_component_database\Datasheet\Capacitor\Capacitor_Walsin_MLCC.pdf
R151-R153 = RES_0: +/-5%; Manufacturer: WALSIN; Part Number: WR02X103 JAL; Datasheet: \\172.29.17.1\cn\WLAN\WLAN2\boarddesignLIB\01_component_database\Datasheet\Resistor\Resistor_Walsin_chipR.pdf
U20 = Flash_0: used for QAB; Manufacturer: Giga
C112 = CAP_NP_2: Y5V, ∮20%, 6.3; Manufacturer: WALSIN; Part Number: 0805F226Z6R3CT; Unit Price(USD): 0.01921
C115 = CAP_NP_3: Y5V, ∮20%, 25V; Manufacturer: WALSIN; Part Number: 0603F104Z250CT; Unit Price(USD): 0.00118
C116 = C_7
C118 = C_4
C119 = C_6
C121 = CAP_NP: Y5V, ∮20%, 6.3; Manufacturer: WALSIN; Part Number: 0805F226Z6R3CT; Unit Price(USD): 0.01921
C122 = C_5
C124 C125 C134 C135 = CAP_NP_1: PartNumber: 0603X106M6R3CT; Specification: X5R; Vendor: 華新
C151 = CAP_NP_5: Y5V, ∮20%, 6.3; Manufacturer: WALSIN; Part Number: 0805F226Z6R3CT; Unit Price(USD): 0.01921
C152 = CAP_NP_1: Y5V, ∮20%, 6.3; Manufacturer: WALSIN; Part Number: 0805F226Z6R3CT; Unit Price(USD): 0.01921
C153 = CAP_NP_6: Y5V, ∮20%, 6.3; Manufacturer: WALSIN; Part Number: 0805F226Z6R3CT; Unit Price(USD): 0.01921
C154 = CAP_NP_4: Y5V, ∮20%, 6.3; Manufacturer: WALSIN; Part Number: 0805F226Z6R3CT; Unit Price(USD): 0.01921
C158 = CAPACITOR_NON-POL_0: 10%,50V,X7R; Manufacturer: WALSIN; Part Number: 0402B102K500CT; Voltage: 50V; Datasheet: \\172.29.17.1\cn\WLAN\WLAN2\boarddesignLIB\74_component_database\Datasheet\Capacitor\Capacitor_Walsin_MLCC.pdf
C159 C160 = CAPACITOR_NON-POL_0: ±20%,6.3V,X5R; Manufacturer: WALSIN; Part Number: 0603X476M6R3CT; Voltage: 6.3V; Datasheet: \\172.29.17.1\cn\WLAN\WLAN2\boarddesignLIB\160_component_database\Datasheet\Capacitor\Capacitor_Walsin_MLCC.pdf
C161 C162 = CAPACITOR_NON-POL_0: ±10%,6.3V,X7R; Manufacturer: WALSIN; Part Number: 0402B105K6R3CT; Voltage: 6.3V; Datasheet: \\172.29.17.1\cn\WLAN\WLAN2\boarddesignLIB\83_component_database\Datasheet\Capacitor\Capacitor_Walsin_MLCC.pdf
J8 = CON6_10
J9 = CON6_26
J1 J2 J10 = CON2
J11 = CON6_24
P1 = PAD
Q1 = MOSFET_P: P沟道 20V 1.6A; Manufacturer: TECH PUBLIC; Part Number: FDN338P; Datasheet: \\172.29.17.1\cn\WLAN\WLAN2\boarddesignLIB\01_component_database\Datasheet\Triode-MOS Tube-Transistor\P-MOS_TECH PUBLIC_FDN338P_2021-09-03.pdf
R81 R83 R84 R87 R90 R91 R93 = RES_0: +/-1%; Manufacturer: WALSIN; Part Number: WR02X27R0FAL; Datasheet: \\172.29.17.1\cn\WLAN\WLAN2\boarddesignLIB\01_component_database\Datasheet\Resistor\Resistor_Walsin_chipR.pdf
R82 R89 R94 R98 R99 R105 R110 R140 R145-R150 = RES_0: JUMPER; Manufacturer: WALSIN; Part Number: WR02X000PTL; Datasheet: \\172.29.17.1\cn\WLAN\WLAN2\boarddesignLIB\01_component_database\Datasheet\Resistor\Resistor_Walsin_chipR.pdf
R1 R2 R4 R5 R7 R14 R15 R17 R19 R20 R109 R135 R136 R143 R144 = RES_V: Manufacturer: WALSIN; Part Number: WR04X4700FTL; Unit Price(USD): 0.00032
R11-R13 R16 R18 R111 = RESISTOR
R24 R121 = R_2
R154 = RES_0: JUMPER; Manufacturer: WALSIN; Part Number: WR06X000PTL; Datasheet: \\172.29.17.1\cn\WLAN\WLAN2\boarddesignLIB\01_component_database\Datasheet\Resistor\Resistor_Walsin_chipR.pdf
R155 R157 R158 = RES_0: +/-1%; Manufacturer: WALSIN; Part Number: WR04X1002 FTL; Datasheet: \\172.29.17.1\cn\WLAN\WLAN2\boarddesignLIB\01_component_database\Datasheet\Resistor\Resistor_Walsin_chipR.pdf
R156 = RES_0: +/-1%; Manufacturer: WALSIN; Part Number: WR04X1001FTL; Datasheet: \\172.29.17.1\cn\WLAN\WLAN2\boarddesignLIB\01_component_database\Datasheet\Resistor\Resistor_Walsin_chipR.pdf
SD16 = DIODE_1: 肖特基二极管,30V 1A 440mV@1A; Manufacturer: Vishay; Part Number: MSS1P3L-M3/89A; Datasheet: \\172.29.17.1\cn\WLAN\WLAN2\boarddesignLIB\01_component_database\Datasheet\Diode\Diode_Vishay_MSS1P3L.pdf
U16 = FPC-24_4
U17 = CAT7103_1: ID: A
U18 = FPC-10P
C3 = CAP_NP_5: NPO, ∮10%, 50V; Manufacturer: WALSIN; Part Number: 0402B102K500CT; Unit Price(USD): 0.00076
C4 = CAP_NP_1: NPO, ∮10%, 50V; Manufacturer: WALSIN; Part Number: 0402B102K500CT; Unit Price(USD): 0.00076
C5 = CAP_NP_8: NPO, ∮10%, 50V; Manufacturer: WALSIN; Part Number: 0402B102K500CT; Unit Price(USD): 0.00076
C7 = CAP_NP_9: NPO, ∮10%, 50V; Manufacturer: WALSIN; Part Number: 0402B102K500CT; Unit Price(USD): 0.00076
C8 = CAP_NP: Y5V, ∮20%, 25V; Manufacturer: WALSIN; Part Number: 0603F104Z250CT; Unit Price(USD): 0.00118
C9 = CAP_NP_6: NPO, ∮10%, 50V; Manufacturer: WALSIN; Part Number: 0402B102K500CT; Unit Price(USD): 0.00076
C10 = CAP_NP_7: Y5V, ∮20%, 6.3; Manufacturer: WALSIN; Part Number: 0805F226Z6R3CT; Unit Price(USD): 0.01921
C12 = C_v2_5: X7R, ∮10%, 10V; Manufacturer: WALSIN; Part Number: 0402B104K100CT; Unit Price(USD): 0.0008
C13 = C_v2_4: X7R, ∮10%, 10V; Manufacturer: WALSIN; Part Number: 0402B104K100CT; Unit Price(USD): 0.0008
C70 C75 C132 C133 = CAPACITOR_NON-POL_0: ±5%,25V,NPO,Y; Manufacturer: WALSIN; Part Number: 0201N100J250CT; Voltage: 25V; Datasheet: \\172.29.17.1\cn\WLAN\WLAN2\boarddesignLIB\51_component_database\Datasheet\Capacitor\Capacitor_Walsin_MLCC.pdf
C141 = CAP_NP_4: NPO, ∮10%, 50V; Manufacturer: WALSIN; Part Number: 0402B102K500CT; Unit Price(USD): 0.00076
C142 = CAP_NP_3: NPO, ∮10%, 50V; Manufacturer: WALSIN; Part Number: 0402B102K500CT; Unit Price(USD): 0.00076
C143 = C_1: X7R, ∮10%, 10V; Manufacturer: WALSIN; Part Number: 0402B104K100CT; Unit Price(USD): 0.0008
CON1 = USB_TYPE_C: Manufacturer: Molex; Part Number: 2171790001
CON2 = USB_CON_1X4P_ACON_3: CONTECK/22133-4W21-01; Class: IO; Colay_Alternate: N/A; Colay_Group: N/A; Component_Name: USB CON 1X4P,M,A TYPE,R/A,SMT; Critical_Part: N; Data_Sheet: K:\DataSheet\12-CONNECTOR\1213-003Q000.zip; Database_Update: 2009/2/7; Device: hh_usb_1x4p_4hd_m_ra_lf3; Electric_SPE: WHITE; FPLIST: hh_usb_1x4p_4hd_m_ra_lf3,usb_1x4p_4hd_m_ra_lf3; Green_HF: GA; HsFlag: A000000000; Manufacture: CONTECK; Modify_data: 2011/11/03; Optional: N/A; Package_Type: SMD; Part Number: 1213-003Q000; Part Type: 12CONNECTOR\USB; Sourcer: ¶À±Ò©ú(LA0803562); Subsystem_ID: N/A; Symbol_pic: K:\Symbol_Pic\12-CONNECTOR\1213-003Q000_MID.zip; metal_fabrication: 000000X100
D1-D3 = LED_0
H1-H4 = HOLE_PTH: FOR PEGATRON ENTEK; Colay_Alternate: N/A; Colay_Group: N/A; Component_Name: TOOLING HOLE C205D126; Data_Sheet: K:\DataSheet\13-MECHANICAL\T-SH00002166.zip; Device: hole_c205d126; Modify_data: 2013/01/17; Optional: N/A; Package_Type: DIP; Part Number: T-SH00002166; Part Type: 13MECHANICAL\HOLE; Subsystem_ID: N/A
K1-K5 = BUTTON_(RST)_2: Part Number: TAVPCM01-038ST-R
R21-R23 = RES_V: Manufacturer: WALSIN; Part Number: WR04X1003FTL; Unit Price(USD): 0.00032
R29 = R_4
U1 = USB2UART_0
U2 = RL5760_4
U3 = CAT7103_0: ID: A
U4 = CAT7103_2: ID: A
U19 = LT1084-3_3.3

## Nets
GND: ANT1.2(G) ANT1.4(G) C1.2 C3.2 C4.2 C5.2 C7.2 C9.2 C10.2 C11.2 C13.2 C14.2 C15.1 C16.1 C17.1 C18.1 C19.1 C20.1 C21.1 C22.1 C23.1 C24.1 C25.2 C26.1 C27.1 C28.2 C29.2 C30.1 C31.2 C32.2 C33.2 C34.1 C35.1 C36.1 C37.1 C38.2 C39.2 C40.2 C41.1 C42.1 C43.2 C44.1 C46.2 C47.2 C48.1 C49.1 C50.2 C51.1 C52.1 C53.1 C54.1 C55.1 C56.2 C57.2 C58.2 C59.1 C60.1 C61.1 C62.1 C63.1 C64.1 C65.1 C66.1 C67.2 C68.1 C69.1 C70.2 C71.2 C72.1 C73.1 C74.1 C75.2 C76.2 C77.2 C78.2 C79.2 C80.1 C81.1 C82.2 C84.1 C85.1 C87.1 C88.1 C89.1 C90.1 C91.1 C95.2 C96.2 C97.2 C108.2 C109.1 C110.1 C111.1 C112.2 C113.2 C114.2 C115.1 C116.2 C117.2 C118.2 C119.2 C120.1 C121.2 C122.2 C123.2 C124.2 C125.2 C130.2 C131.1 C132.2 C133.2 C134.2 C135.2 C137.1 C139.1 C140.2 C141.2 C142.1 C143.1 C144.2 C147.1 C148.1 C149.1 C150.1 C151.2 C152.2 C153.2 C154.2 C155.2 C156.2 C157.2 C159.2 C160.2 C161.2 C162.2 CON1.1(GND) CON1.8(GND) CON1.9(GND) CON1.16(GND) CON2.5(GND) IPEX2.2(G) IPEX2.3(G) IPEX3.2(G) IPEX3.3(G) J3.1 J5.3(GND1) J5.4(GND2) J8.6 J8.9 J8.14 J8.20 J8.25 J8.30 J8.34 J8.39 J9.5 J9.6 J9.11 J9.12 J10.1 J11.5 J11.6 JP2.2 JP3.2 K1.3 K1.4 L15.1 L16.2 P1.6(VSSQ/VSS) P1.10(VSS) P1.12(GND1) P1.13(GND2) P1.14(GND3) P1.15(GND4) R3.2 R5.1 R14.1 R16.2 R17.1 R18.2 R19.2 R23.1 R24.1 R34.2 R38.1 R51.1 R58.2 R63.2 R67.1 R68.2 R70.1 R71.1 R74.2 R75.2 R111.2 R126.1 R127.1 R128.1 R129.2 R130.2 R132.1 R157.2 R158.2 SD1.2 SD2.2 SD3.2 SD4.2 SD5.2 SD6.2 SD7.2 SD8.2 SD9.2 SD10.2 SD11.2 SD12.2 SD13.2 SD14.2 SD15.2 SD17.2(CATHODE) SD20.2(CATHODE) SD21.2(CATHODE) SD22.2(CATHODE) SD23.2(CATHODE) SD24.2(CATHODE) SD25.2(CATHODE) SD27.2 SD28.2 SD29.2 SD30.2 SD31.2 SD32.2(CATHODE) SD33.2 SD34.2 SD35.2 SD36.2 SD37.2 SD38.2 SD39.2 SD40.2 SD41.2 SD42.2 TP1.1 TP3.1 U1.1(GND) U1.5(GND) U2.25(GND) U3.2(GND) U5.4(GND_DCDC_CORE) U5.30(GND) U5.74(GND_DCDC_MEM) U5.99(GND_DCDC_AUD) U5.101(EPAD_GND) U6.1(GND) U6.3(GND) U6.5(GND) U7.7(GND) U8.5(GND) U8.6(GND) U8.7(GND) U8.8(GND) U9.1(GND) U9.2(GND) U9.3(GND) U9.5(GND) U10.1(GND) U10.2(GND) U10.3(GND) U10.5(GND) U11.1(GND) U11.2(GND) U11.3(GND) U11.5(GND) U12.2(L/R) U12.5(GND) U12.6(GND) U12.7(GND) U12.8(GND) U13.3(LINP) U13.4(LINN) U13.8(AGND) U13.19(PGND2) U13.24(PGND1) U13.29(GND) U14.1(GND) U14.2(GND) U14.3(GND) U14.5(GND) U15.2 U16.3(GND) U16.6(GND) U16.9(GND) U16.12(GND) U16.15(GND) U16.21(GND) U16.23(GND) U16.49(GND) U16.50(GND) U17.2(GND) U18.10 U18.11(GND) U18.12(GND) U20.4(GND) X1.2(GND) X1.4(GND)
PVCC: C77.1 C78.1 C79.1 C95.1 C96.1 C97.1 R52.2 R54.2 R62.2 TP6.1 U13.15(PVCCR2) U13.16(PVCCR1) U13.27(PVCCL2) U13.28(PVCCL1)
V33SD_IN: C120.2 C121.1 P1.4(VCCQ/VDD) P1.11(VCC) R100.1 R101.1 R102.1 R103.1 R104.1 R107.1 R109.1 SD36.1 SD42.1
VBUS: CON2.1(VBUS) R15.2 R20.2 SD6.1
VCCIO: C142.2 R1.2 R2.2 R4.1 R7.1 U1.8(VCC_IO) U2.24(VDD_IO)
VDD5V: C4.1 C10.1 C11.1 CON1.2(VBUS) CON1.7(VBUS) CON1.10(VBUS) CON1.15(VBUS) J8.2 J8.4 R12.1 R20.1 R54.1 SD1.1 TP4.1 U1.2(5V_OUT) U1.3(5V_OUT) U1.4(5V_IN) U2.14(VIN) U3.5(VIN)
VDD09: C18.2 C21.2 C22.2 C23.2 C38.1 C39.1 C42.2 C43.1 C50.1 L4.1 U5.11(VDL_CORE) U5.56(VDL_CORE) U5.64(VDL_CORE) U5.77(VAL_USB) U5.84(VAL_MIPI) U5.87(VDL_CORE) U5.98(VDL_CORE)
VDD18_A: C26.2 C27.2 L2.1 R33.1
VDD18_D: C29.1 C31.1 C32.1 C33.1 C34.2 C35.2 L3.2 R32.2 R134.1 U5.61(VDM_MEM) U5.62(VDM_MEM) U5.65(VDM_MEM)
VDD18_R: C48.2 C51.2 C52.2 C55.2 C64.2 R33.2 R134.2 U5.19(VAM_AFE) U5.23(VRM_SYN) U5.25(VRM_RF) U5.36(VRM_FE_BT) U5.53(VAM_AUD)
VDD33: C12.1 C13.1 C14.1 C159.1 C160.1 D3.1 J8.1 J8.17 JP1.1 K3.1 K3.2 K4.1 K4.2 K5.1 K5.2 L1.2 Q1.2(SOURCE) R7.2 R11.1 R13.1 R42.2 R48.2 R56.2 R72.1 R109.2 R116.2 R118.2 R119.2 R121.2 R124.2 R125.2 R154.1 R155.1 TP2.1 U4.2(VDD)
VDD33_LCD: C112.1 C113.1 C158.1 L12.1 Q1.3(DRAIN) R108.1 R154.2 U16.1(VDDIO_3V3) U16.2(VDD_3V3) U17.6(VIN)
VDD33_S: C19.2 C20.2 C24.2 C25.1 C36.2 C37.2 C40.1 C41.2 C44.2 C54.2 C59.2 C60.2 C61.2 C62.2 C63.2 C65.2 C156.1 C157.1 JP1.2 R11.2 R21.2 R22.2 R137.2 R139.1 R151.1 R152.1 R153.2 U5.1(VAH_DCDC_AUD) U5.2(VAH_DCDC_CORE) U5.9(VDH_IO0) U5.14(VDH_IO1) U5.24(VRH_SYN) U5.26(VRH_PAD_A) U5.27(VRH_PA_A) U5.33(VRH_PA_G) U5.34(VRH_PAD_G) U5.35(VRH_FE_BT) U5.38(VRH_PA_BT) U5.70(VDH_IO3) U5.76(VAH_DCDC_MEM) U5.88(VDH_IO5) U5.93(VDH_IO6___|___VDH_IO6) U20.8(VCC)
1SD_CD: C80.2 P1.9(CD) R93.2 R103.2 SD40.1
1SD_CLK: C119.1 P1.5(CLK) R87.2 SD37.1
1SD_CMD: C118.1 P1.3(CMD) R84.2 R102.2 SD35.1
1SD_D0: C123.1 P1.7(D0) R90.2 R104.2 SD38.1
1SD_D1: C122.1 P1.8(D1) R91.2 R107.2 SD39.1
1SD_D2: C116.1 P1.1(D2) R81.2 R100.2 SD41.1
1SD_D3: C117.1 P1.2(D3) R83.2 R101.2 SD34.1
ANT_SEL_N: C131.2 R141.1 U7.2(Vc2)
ANT_SEL_P: C130.1 R142.1 U7.5(Vc1)
AOUT_LP: C94.1 J7.1 R71.2
AOUT_LPE: C106.1 J7.3
BAT_MEAS: J10.2 U5.10(BAT_MEAS)
BLEN: C162.1 R78.1 R108.2 R158.1 U17.4(EN)
BT_ANT: C127.1 R36.1
CC1: CON1.3(CC1) R132.2
CC2: CON1.11(CC2) R3.1
CHIP_EN: C15.2 K1.1 K1.2 R21.1 R143.1 SD7.1 U5.71(CHIP_EN)
DSI_CK: U5.83(DSI_CP) U16.10(DSI_CP)
DSI_CN: U5.82(DSI_CN) U16.11(DSI_CN)
DSI_DN0: U5.85(DSI_DN0) U16.8(DSI_DN0)
DSI_DN1: U5.80(DSI_DN1) U16.14(DSI_DN1)
DSI_DP0: U5.86(DSI_DP0) U16.7(DSI_DP0)
DSI_DP1: U5.81(DSI_DP1) U16.13(DSI_DP1)
DTR_N: R136.2 U2.22(DTR_N) U19.1(E0)
FT_LOG_RX: J2.2 R8.1 U1.7(FT232_RX) U2.1(RXD)
FT_LOG_TX: J1.2 R6.1 U1.6(FT232_TX) U2.21(TXD)
HSDM: R10.2 U5.79(HSDM)
HSDM_USB: C132.1 CON2.2(D-) R10.1 SD5.1
HSDP: R9.2 U5.78(HSDP)
HSDP_USB: C133.1 CON2.3(D+) R9.1 SD4.1
LCD_CTP_INT: R96.1 U16.17(I2C_INT)
LCD_CTP_RST: R95.1 U16.16(I2C_RST)
LCD_CTP_SCL: R85.1 U16.5(I2C_SCL)
LCD_CTP_SDA: R80.1 U16.4(I2C_SDA)
LCD_Power_EN#: C158.2 C161.1 Q1.1(GATE) R155.2 R156.2
LCD_PWM: R97.1 U16.19(LCD_PWM)
LCD_RESET: R88.1 R157.1 U16.18(LCD_RESET)
LCD_TE: R86.1 U16.20(LCD_TE)
LEDA: C114.1 C115.2 SD16.1 U16.24(BLA) U17.5(OV)
LEDB: R31.1 U4.4(Blue)
LEDG: R27.1 U4.3(Green)
LEDK: R111.1 U16.22(BLK) U17.3(FB)
LEDR: R25.1 U4.1(Red)
LINEOUTLN: J11.2 R69.2 U5.51(LINEOUTLN)
LINEOUTLP: J7.2 J11.1 U5.52(LINEOUTLP)
LINEOUTRN: J11.4 U5.55(LINEOUTRN)
LINEOUTRP: C104.1 J11.3 U5.54(LINEOUTRP)
MIC1_N: C99.2 R128.2
MIC1_P: C72.2 C98.2 SD10.1 U9.4(OUT)
MIC2_N: C101.2 R129.1
MIC2_P: C73.2 C100.2 SD11.1 U10.4(OUT)
MIC3_N: C103.2 R130.1
MIC3_P: C74.2 C102.2 SD12.1 U14.4(OUT)
MIC5_N: C107.2 C138.2 R63.1 R64.2
MIC5_P: C105.2 C136.2 R59.2 R60.1
MIC_BIAS1: J9.13 R43.1 R44.1 U5.49(MICBIAS1)
MIC_BIAS2: J9.14 R45.1 R57.1 R92.1 U5.50(MICBIAS2)
MICIN1N: C99.1 J9.2 U5.46(MICIN1N)
MICIN1P: C98.1 J9.1 U5.45(MICIN1P)
MICIN2N: C101.1 J9.4 U5.44(MICIN2N)
MICIN2P: C100.1 J9.3 U5.43(MICIN2P)
MICIN3N: C103.1 J9.8 U5.42(MICIN3N)
MICIN3P: C102.1 J9.7 U5.41(MICIN3P)
MICIN5N: C107.1 J9.10 U5.40(MICIN5N)
MICIN5P: C105.1 J9.9 U5.39(MICIN5P)
OUT_ANT1: C57.1 C128.1 L6.1
OUT_ANT2: C68.2 C129.2 L7.1
PA2: R112.2 R113.2 U5.5(PA2)
PA3: R114.2 R117.2 U5.6(PA3)
PA4: R115.2 R120.2 U5.7(PA4)
PA5: R122.2 R123.2 U5.8(PA5)
PA9: J8.26 R96.2 U5.12(PA9)
PA10: J8.15 R25.2 R95.2 U5.13(PA10)
PA13: C134.1 J8.19 R27.2 R97.2 U5.15(PA13)
PA14: C135.1 J8.21 R31.2 R88.2 U5.16(PA14)
PA15: J8.23 R86.2 R138.2 U5.17(PA15)
PA16: J8.24 R78.2 R156.1 U5.18(PA16)
PA_2: J8.7 R26.2 R112.1
PA_3: J8.11 R114.1
PA_4: J8.12 R115.1 R141.2
PA_5: J8.13 R122.1 R142.2
PA_15: R77.1 R138.1
PA_SD_B: R35.1 R53.2
PB10: C151.1 J8.3 R80.2 R116.1 U5.57(PB10)
PB11: C152.1 J8.5 R85.2 R118.1 U5.58(PB11)
PB19: R35.2 R39.2 U5.66(PB19)
PB20: J8.8 R15.1 R17.2 U5.67(PB20)
PB21: J11.7 R47.2 R50.2 R124.1 R126.2 U5.68(PB21)
PB22: J11.8 R46.2 R49.2 R125.1 R127.2 U5.69(PB22/TM_DIS)
PB23: C124.1 J1.1 J11.9 R6.2 U5.72(PB23)
PB24: C16.2 C125.1 J2.1 J11.10 K2.1 K2.2 R8.2 R22.1 R144.2 SD8.1 U5.73(PB24/UD_DIS)
PB25: R81.1 R89.1 U5.96(PB25)
PB26: R83.1 R94.1 U5.97(PB26)
PB_19: J8.10 R39.1
PB_25: C153.1 J8.27 R89.2 R119.1
PB_26: C154.1 J8.28 R94.2 R121.1
PB_27: J8.16 R98.2
PB_28: J8.18 R105.2
PB_29: J8.22 R110.2
PB_30: J8.29 R82.2
PB_31: J8.31 R140.2
PC1/PB27: R84.1 R98.1 R145.1 U5.89(PC1____|___________PB27)
PC2/PB28: R87.1 R105.1 R146.1 U5.90(PC2____|___________PB28)
PC3/PB29: R90.1 R110.1 R147.1 U5.91(PC3____|___________PB29)
PC4/PB30: R82.1 R91.1 R150.1 U5.92(PC4____|___________PB30)
PC5/PB31: R140.1 R148.1 U5.94(PC5____|___________PB31)
PC6/PC0: R93.1 R99.1 R149.1 U5.95(PC6__|___________PC0)
PC_0: J8.32 R99.2
RFIO_A: C2.1 L13.2 U5.28(RFIO_A)
RFIO_BT: C45.1 L5.1 U5.37(RFIO_BT)
RFIO_G: C30.2 L14.2 U5.32(RFIO_G)
RTS_N: R135.1 U2.23(RTS_N) U19.4(E1)
SPI_CLK: R146.2 U20.6(SCLK)
SPI_CS: R149.2 R151.2 U20.1(\\~{C}S)
SPI_DATA0: R147.2 U20.5(SI/IO0)
SPI_DATA1: R148.2 U20.2(SO/IO1)
SPI_DATA2: R150.2 R152.2 U20.3(\\~{W}P/IO2)
SPI_DATA3: R145.2 R153.1 U20.7(\\~{HOL}D/IO3)
SPK_N: C89.2 J5.1(S1) L8.1 R65.1 SD15.1
SPK_P: C88.2 J5.2(S2) L9.1 R61.1 SD14.1
TOUCH2_ADC2: R113.1 U18.8
TOUCH3_ADC3: R117.1 U18.7
TOUCH4_ADC4: R120.1 U18.6
TOUCH5_ADC5: R123.1 U18.3
USB_DN: C75.1 CON1.5(DN1) CON1.13(DN2) SD3.1 U2.11(DM)
USB_DP: C70.1 CON1.4(DP1) CON1.12(DP2) SD2.1 U2.10(DP)
VREF_DRAM: C28.1 R32.1 R34.1 U5.63(NC__|__MREF)
WLAN_ANT: C126.2 R40.2
XI: U5.22(XI) X1.1(XTALP)
XO: U5.21(XO) X1.3(XTALP)
N18270071: C46.1 C139.2 C140.1 L5.2 R36.2 R37.2
N18324112: C66.2 U5.47(AUD_VREF)
N18324900: C67.1 U5.48(LDOA_OUT)
N18504985: C53.2 C56.1 R40.1 R41.1 U6.2(ANT)
N18579619: C93.2 U13.17(BSPR) U13.21(BSNR)
N18579620: C93.1 L9.2 U13.18(OUTPR) U13.20(OUTNR)
N18579622: C87.2 R66.1 U13.9(GVDD)
N18579623: C94.2 U13.12(RINP)
N18579624: C84.2 R62.1 U13.7(AVCC)
N18579656: R51.2 R53.1 R55.2 U13.1(~{SD})
N18579665: R55.1 R56.1 U13.2(~{FAULT})
N18579679: C90.2 R66.2 R68.1 U13.10(PLIM)
N18579686: C92.2 U13.11(RINN)
N18579711: C83.2 U13.22(BSNL) U13.26(BSPL)
N18579713: C83.1 L8.2 U13.23(OUTNL) U13.25(OUTPL)
N18579787: C92.1 R69.1 R70.2
N18582001: R47.1 SD30.1 U8.4(DATA)
N18582013: R50.1 SD33.1 U12.4(DATA)
N18582072: C76.1 R48.1 SD29.1 U12.1(VDD)
N18582201: R46.1 SD28.1 U8.3(CLK)
N18582205: R49.1 SD31.1 U12.3(CLK)
N18582241: C71.1 R42.1 SD27.1 U8.1(VDD) U8.2(L/R)
N18582264: C148.2 R43.2 SD21.1(ANODE) U9.6(VDD)
N18582290: C147.2 R44.2 SD20.1(ANODE) U10.6(VDD)
N18601770: C82.1 C86.2 R58.1 R59.1 R61.2
N18601772: C86.1 C91.2 R64.1 R65.2 R67.2
N18642584: C149.2 R45.2 SD22.1(ANODE) U14.6(VDD)
N18644229: C150.2 R57.2 SD23.1(ANODE) U11.6(VDD)
N18644247: C85.2 R60.2 SD13.1 U11.4(OUT)
N18649383: C155.1 R38.2 U5.60(RREF)
N18650190: L2.2 U5.100(LX_AUD)
N18655385: C141.1 R4.2 U2.13(RESET_N)
N18655422: D2.1 R1.1
N18655424: D2.2 U2.16(GPB1)
N18655459: D1.2 U2.15(GPB0)
N18655483: D1.1 R2.1
N18662617: L12.2 SD16.2 U17.1(SW)
N18669482: L3.1 U5.75(LX_MEM)
N18676049: L4.2 U5.3(LX_CORE)
N18716033: C17.2 R24.2 R26.1 R28.2 R29.2 R30.2 SD9.1
N18718623: C5.1 CON1.17(PAD) CON1.18(PAD) CON1.19(PAD) CON1.20(PAD) R5.2
N18739003: J4.1 R52.1
N18756904: JP3.1 L11.2 R74.1 SD25.1(ANODE) U15.4
N18756917: JP2.1 L10.2 R75.1 SD24.1(ANODE) U15.3
N18756961: C138.1 C144.1 R76.1 SD32.1(ANODE) U15.1
N18756963: C104.2 C110.2 L10.1
N18756991: C106.2 C111.2 L11.1
N18757014: C109.2 R73.1 R77.2
N18757018: R72.2 R73.2 SD17.1(ANODE) U15.6
N18781773: C12.2 R13.2 R18.1 U3.3(FB)
N18781810: R12.2 R16.1 U3.4(EN)
N18781892: C8.2 L1.1 U3.6(LX)
N18781944: C8.1 U3.1(BS)
N18800702: K2.3 K2.4 R23.2
N18829386: C9.1 CON2.6(GND) CON2.7(GND) CON2.8(GND) CON2.9(GND) R14.2
N18852843: ANT1.1(ANT1) C58.1 L6.2
N18854700: ANT1.3(ANT2) C69.2 L7.2
N18867798: IPEX2.1(Feed) R41.2
N18871360: C127.2 U7.3(OUT2)
N18871401: C126.1 U7.4(OUT1)
N18871452: C129.1 U7.6(ANT1)
N18871460: C128.2 U7.1(ANT2)
N18941182: D3.2 R19.1
N18988087: C3.1 C7.1 U2.12(VO_33)
N18994882: R135.2 U19.2(B0)
N18994884: R136.1 U19.5(B1)
N18994904: C143.2 R143.2 U19.3(C1)
N19028022: C47.1 R137.1 U5.59(VDH_IO2)
N19048526: C49.2 R139.2 U5.20(VAH_XTAL)
N19140074: R144.1 U19.6(C0)
N19146995: C1.1 L13.1 U6.6(5G)
N19147003: C6.2 L14.1 U6.4(2G)
N19147672: C2.2 L15.2
N19147861: C6.1 L16.1
N19178860: K3.3 K3.4 R28.1
N19178872: K4.3 K4.4 R29.1
N19178884: K5.3 K5.4 R30.1
N19205252: C45.2 C81.2
N19234907: C108.1 C136.1 C137.2 R76.2 R92.2
N19303356: IPEX3.1(Feed) R37.1

Not connected (* = marked no-connect by the designer): CON1 6(SBU1)* 14(SBU2)*; CON2 4(ID)*; H1 1*; H2 1*; H3 1*; H4 1*; J8 33* 35* 36* 37* 38* 40*; U2 2(RI_N)* 3(TXEN)* 4(DSR_N)* 5(DCD_N)* 6(CTS_N)* 7(SUSP_N)* 8(GPB3)* 9(GPB2)* 17(GPB4)* 18(GPB5)* 19(XI)* 20(XO)*; U5 29(RFIN_A)* 31(RFIN_G)*; U13 5(NC1)* 6(NC2)* 13(NC3)* 14(NC4)*; U15 5*; U16 25(NC)* 26(NC)* 27(NC)* 28(NC)* 29(NC)* 30(NC)* 31(NC)* 32(NC)* 33(NC)* 34(NC)* 35(NC)* 36(NC)* 37(NC)* 38(NC)* 39(NC)* 40(NC)* 41(NC)* 42(NC)* 43(NC)* 44(NC)* 45(NC)* 46(NC)* 47(NC)* 48(NC)*; U18 1* 2* 4* 5* 9*

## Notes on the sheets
sheet 1
- USB  & POWER
- USB  TYPE C (Device and FT232)
- PL2303GC QFN24 4X4
  USB TO UART
- USB (micro-B)
- 90ohm
- Auto-download Circuit
- 5V --> 3.3V SWR
- Chip_EN SW CTRL
- SW CTRL
- UART_DL SW CTRL
- Func.
- SW CTRL
- Func.
- Press
- Pull LOW
- Press
- Pull LOW
- Power LED
- Release
- Pull HIGH
- Chip_EN
- UART_DOWNLOAD
- Release
- Pull HIGH
- USER KEY
- USER LED
- R_up / Kohm   Vadc / V
      47         0.5789
      34         0.75
      24.9       0.9456
      19.728     1.11
      16.277     1.2599
      14.374     1.3539
      11.007     1.5709
sheet 2
- RTL8730EA_QFN100
- RTL8730EAH
- XTAL
- RTL8730EAM
- BT RF
- C139/C140 ESD optional
  but recommended
- RTL8730EAH-VA3
  RTL8730EAH-VD3
- RTL8730EAH-VH6
  RTL8730EAM-VA6
- When dedicated BT is not used, components of "BT RF"
  can be NC,and the DPDT(U7) can be replaced by SPDT.
- For BT & WLAN coexsitence, C81 is added additionally,
  meanwhile the value of C45 should be changed to 0.8nH
  & C81 to be 1pF
- WLAN RF
- For FCC TX Harmonic
- For CE RX Spurious
- When dedicated BT is not used,
  Pin37 & Pin38 can be NC.
- C53/C56 ESD optional
  but recommended
- For BT & WLAN coexsitence, L16 & L15  are added additionally.
  If pcb placement space is enough, L16 will be better to placed
  at the middle of C30 and ground.
  Meanwhile, the value of C30 should be changed to 0.6nH, L16 to be
  1pF, C2 to be 2.4nH & L15 to be 1.8pF.
- Close to pin63
- ANT
- VREF_DRAM is used only for
  RTL8730EAH-VH6 & RTL8730EAM-VA6
sheet 3
- AUDIO
- DMIC
- AMIC
- Left : DMIC1   L/R=HIGH，CLK=HIGH,DATA=VALID
  Rignt: DMIC2   L/R=LOW，CLK=LOW,DATA=VALID
- SPEAKER
- Colay
- AEC
- L
- R
- GND
- GND
- Earphone Jack (CTIA)
- Note: MIC cap above should close to 8730EA
sheet 4
- Peripheral
- MIPI DSI
- 4 INCH TFT LCD
- SD Card/EMMC
- Colay
- ESD components put close to SD socket
- When RTL8730EAM is mounted, 0 ohm jumping resistors of GPIO nets
  connected with flash such as PB27, PB28, PB29, PB30, PB31, PC0 can be
  removed. It means these GPIOs can be directly connnected to corresponding
  Flash nets
- Realtek 7inch LCD:
  R111=2.2Ω
  Realtek 3.97inch LCD:
  R111=10Ω
- 0603
- GPIOs
- Captouch
- Reserve for internal test
sheet 5
- External FLASH
- Importance!
- 1, External flash is only needed for RTL8730EAM, not for RTL8730EAH.
  It's necessary to configure the correct pull-up or pull-down.
  resistor for PB21 according to the external flash type, which means:
- High for NOR flash and Low for NAND flash.
- NOR FLASH
- PULL UP
- R124 Mounted
- NAND FLASH
- PULL DOWN
- R126 Mounted
